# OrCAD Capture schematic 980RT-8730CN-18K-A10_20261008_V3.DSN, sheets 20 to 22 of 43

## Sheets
20 P0061_S6_DUT1: size Custom
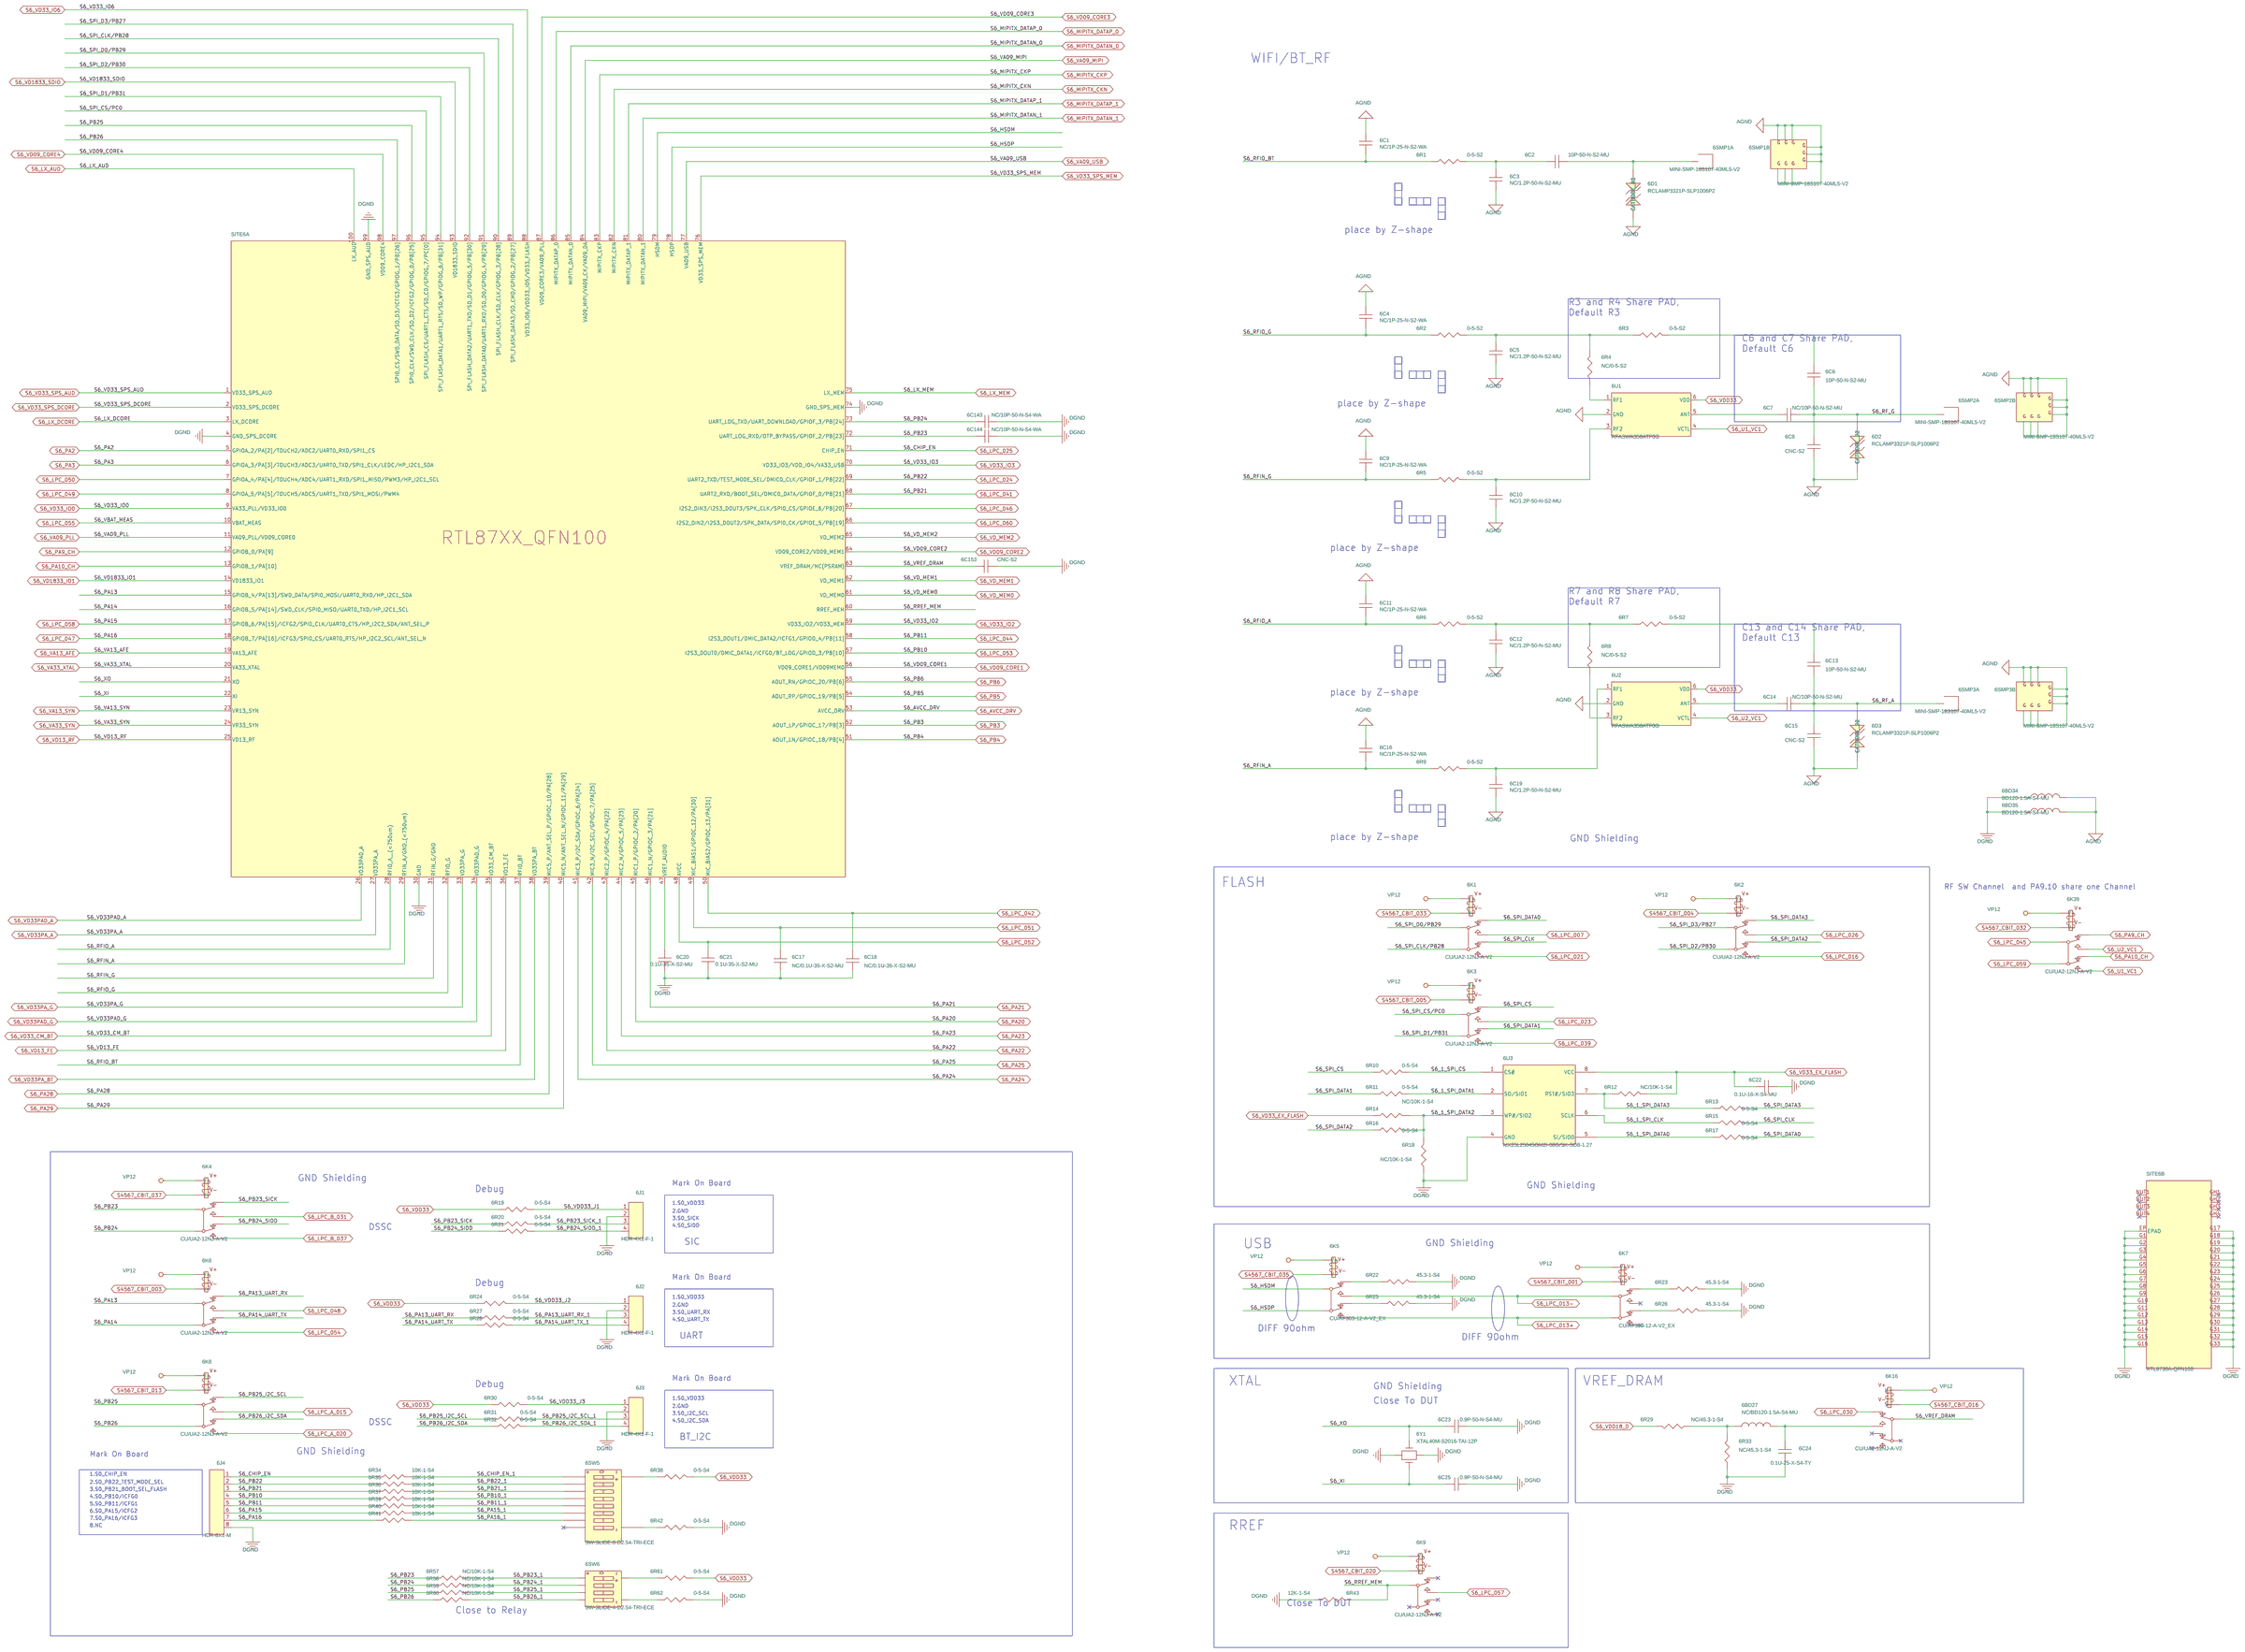
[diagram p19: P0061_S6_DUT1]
21 P0062_S6_Function-test: size A3
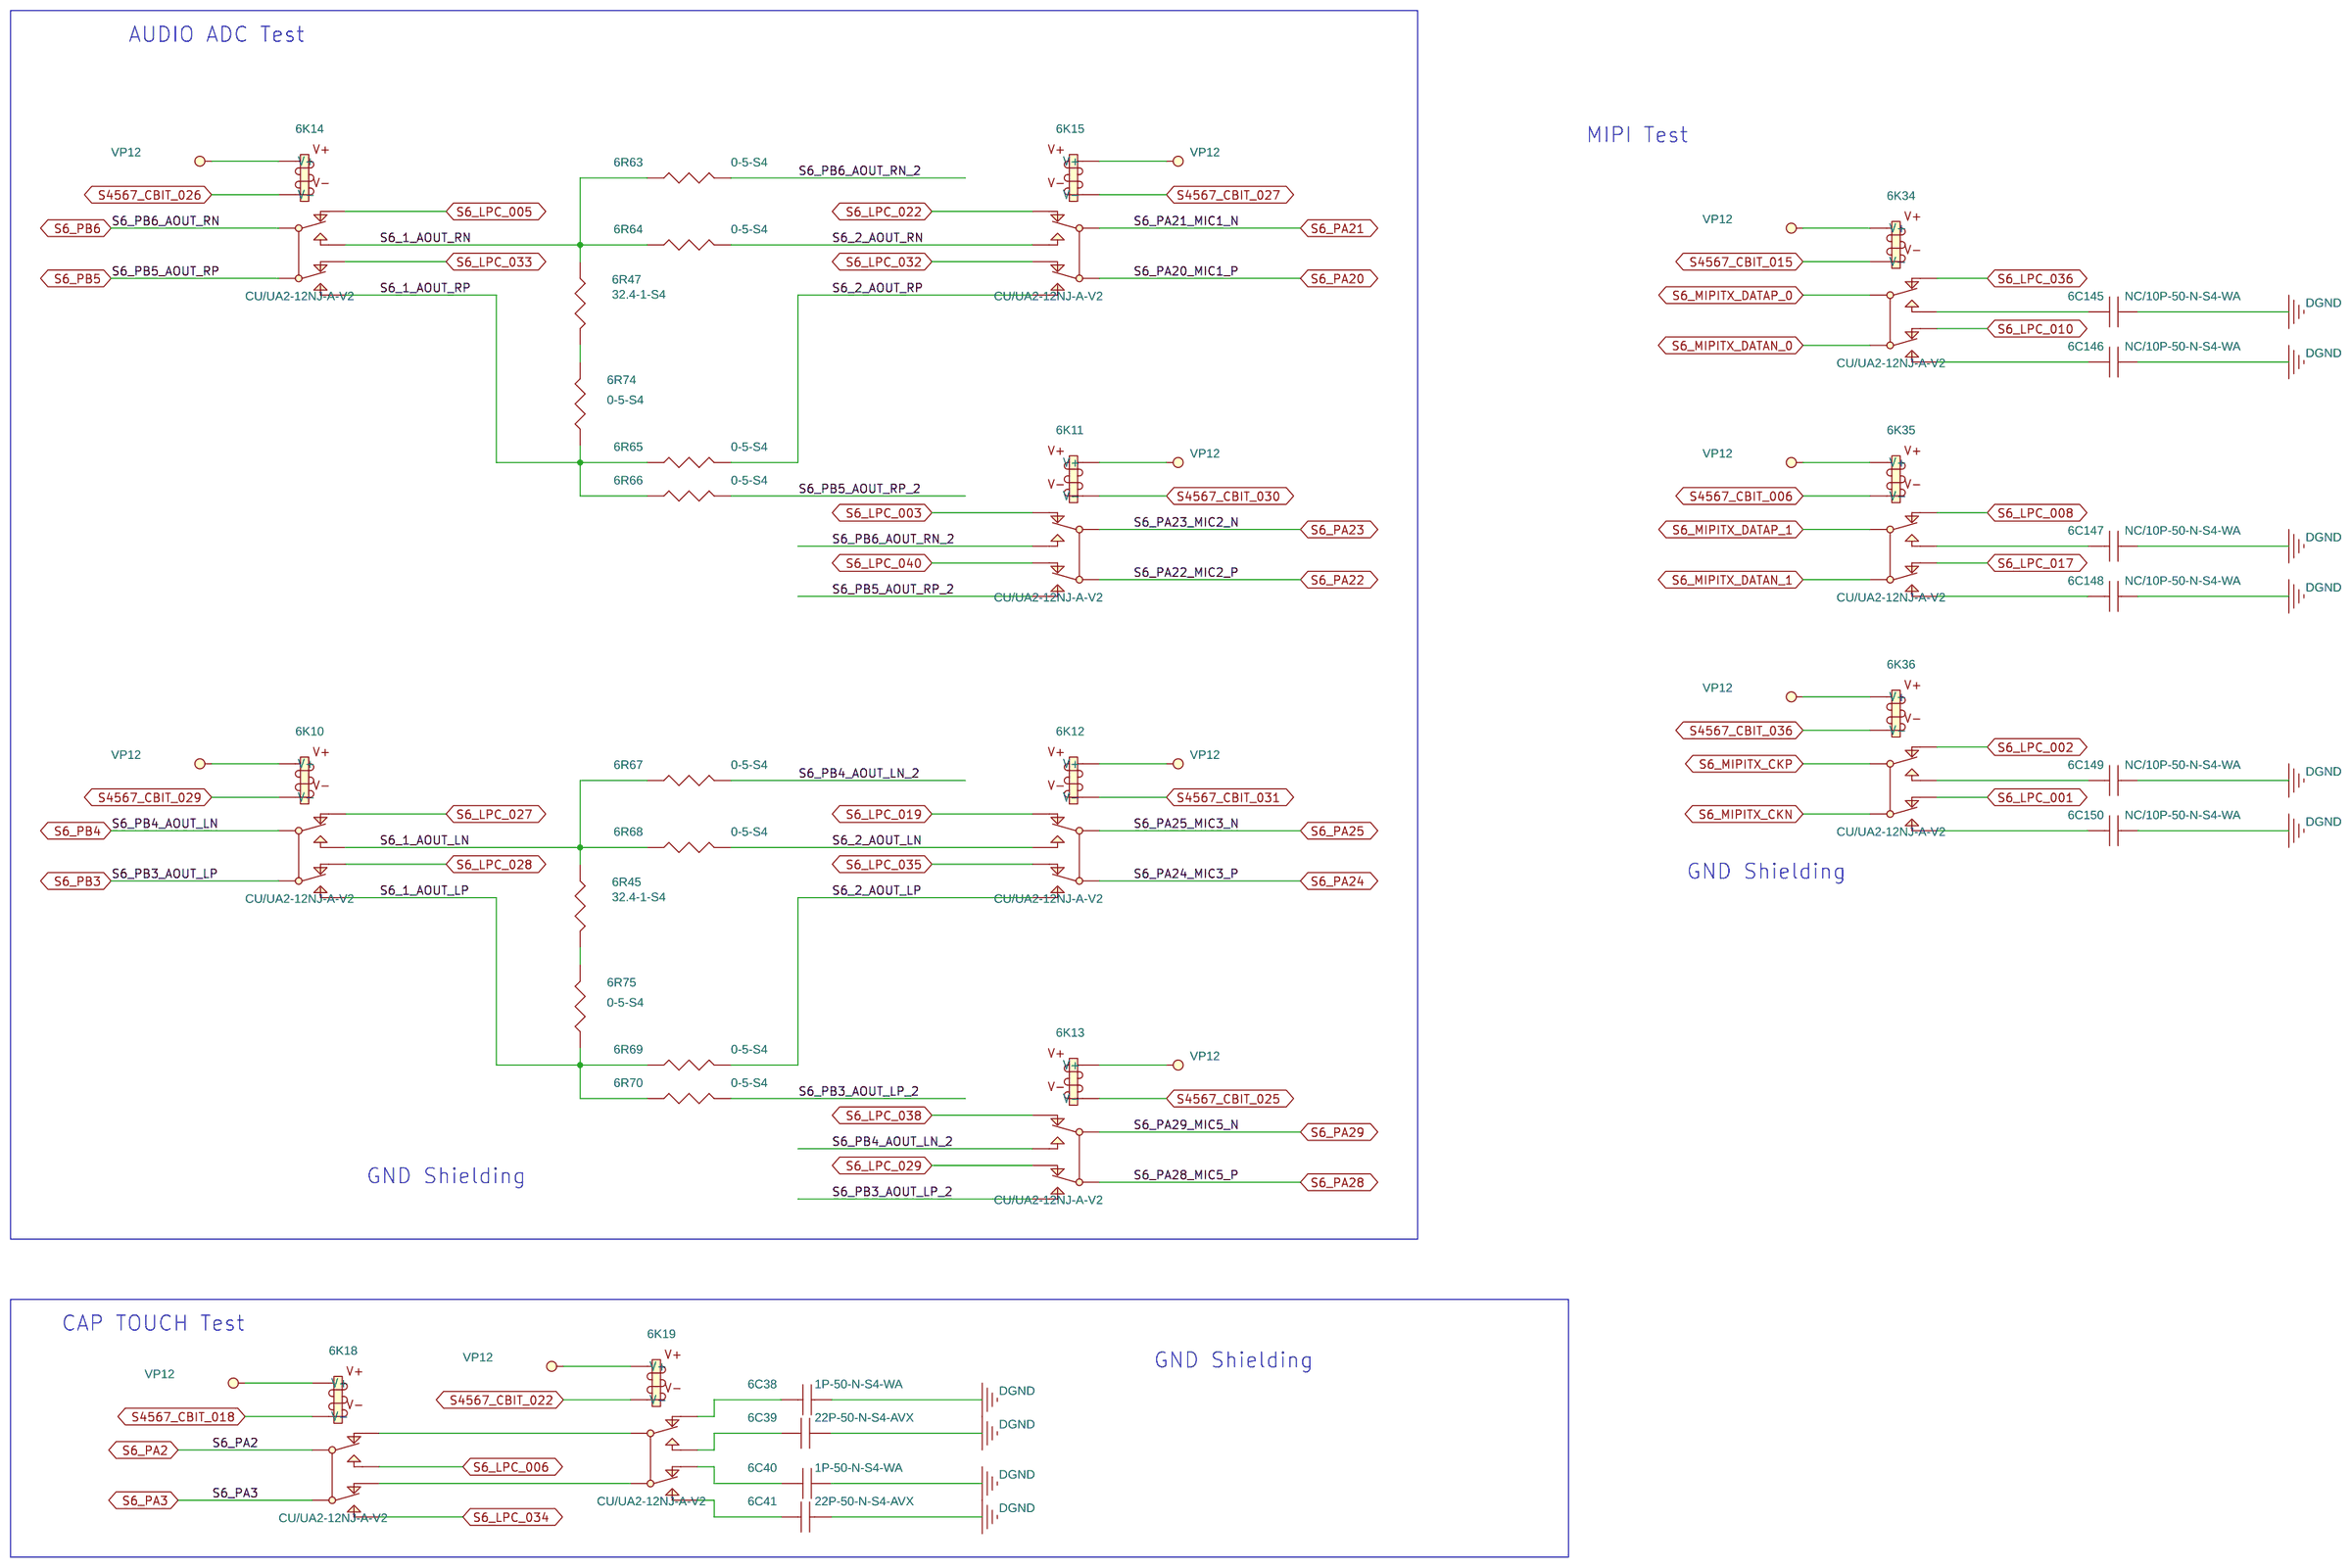
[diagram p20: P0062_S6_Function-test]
22 P0063_S6_Power: size A1
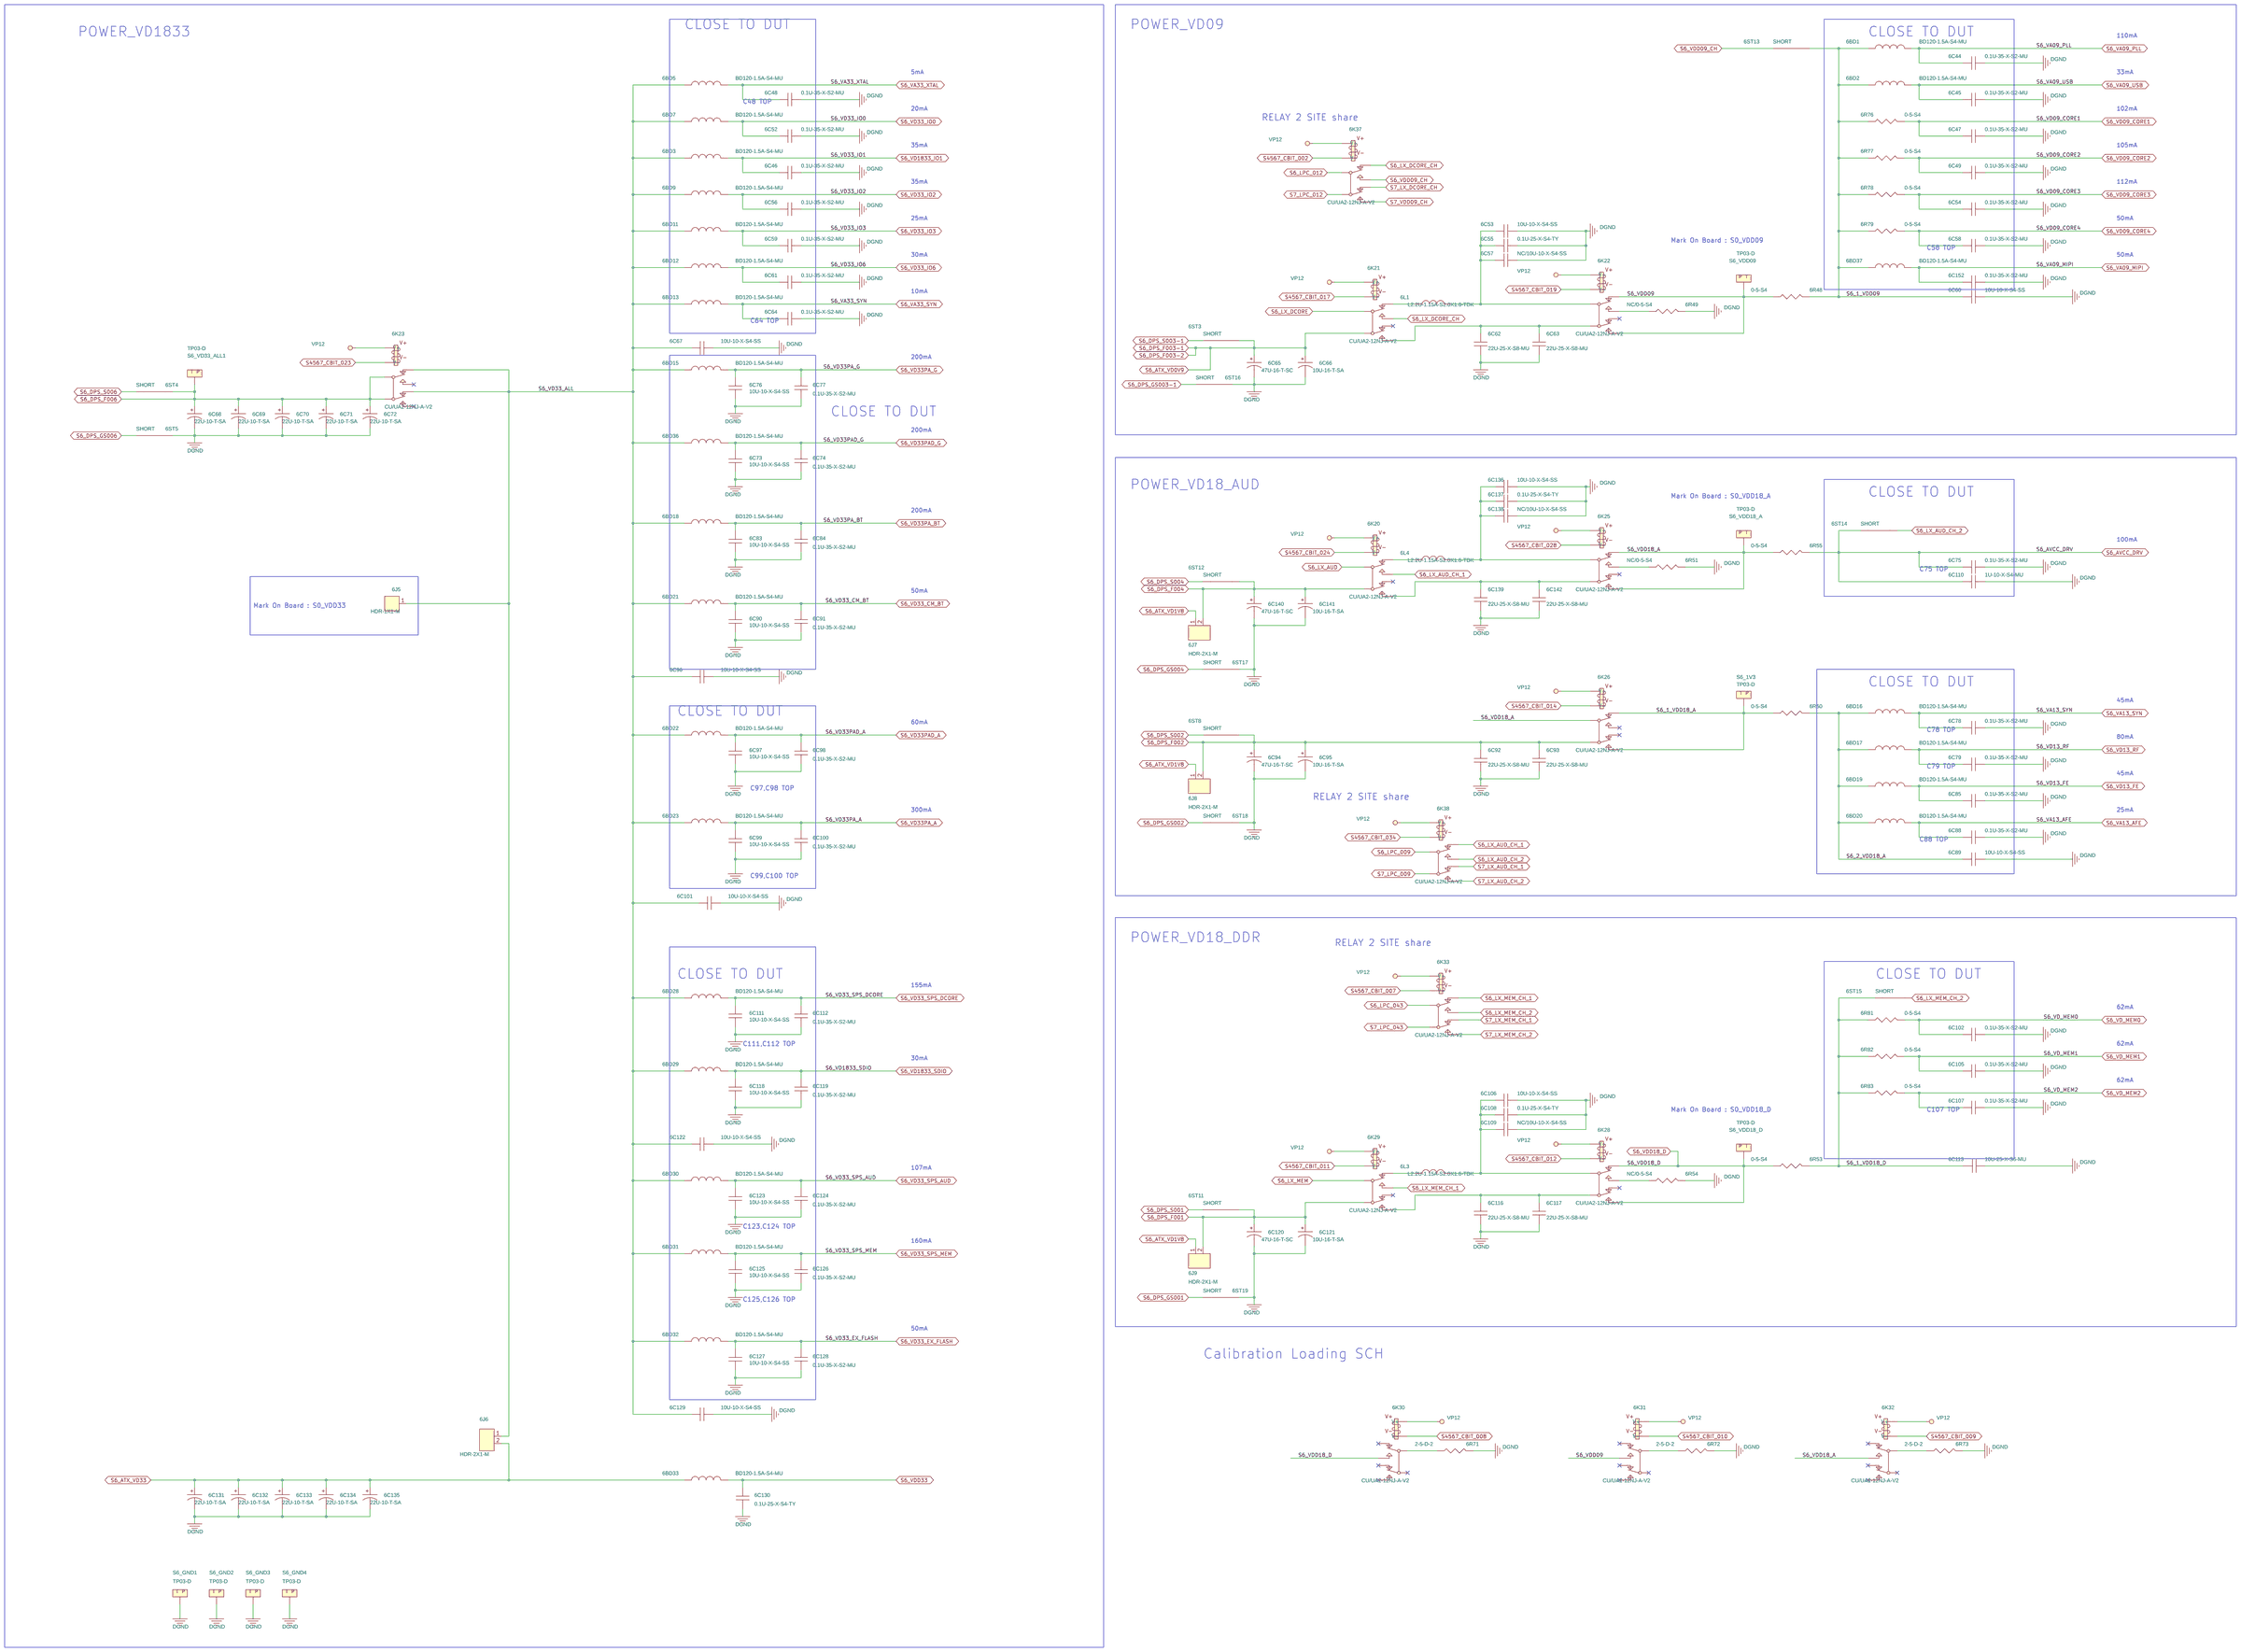
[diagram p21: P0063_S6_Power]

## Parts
sheet P0061_S6_DUT1
6BD27  NC/BD120-1.5A-S4-MU  [FB0402]
6BD34  BD120-1.5A-S4-MU  [FB0402]
6BD35  BD120-1.5A-S4-MU  [FB0402]
6C1  NC/1P-25-N-S2-WA  [C0201]
6C2  10P-50-N-S2-MU  [C0201]
6C3  NC/1.2P-50-N-S2-MU  [C0201]
6C4  NC/1P-25-N-S2-WA  [C0201]
6C5  NC/1.2P-50-N-S2-MU  [C0201]
6C6  10P-50-N-S2-MU  [C0201]
6C7  NC/10P-50-N-S2-MU  [C0201]
6C8  CNC-S2  [C0201]
6C9  NC/1P-25-N-S2-WA  [C0201]
6C10  NC/1.2P-50-N-S2-MU  [C0201]
6C11  NC/1P-25-N-S2-WA  [C0201]
6C12  NC/1.2P-50-N-S2-MU  [C0201]
6C13  10P-50-N-S2-MU  [C0201]
6C14  NC/10P-50-N-S2-MU  [C0201]
6C15  CNC-S2  [C0201]
6C16  NC/1P-25-N-S2-WA  [C0201]
6C17  NC/0.1U-35-X-S2-MU  [C0201]
6C18  NC/0.1U-35-X-S2-MU  [C0201]
6C19  NC/1.2P-50-N-S2-MU  [C0201]
6C20  0.1U-35-X-S2-MU  [C0201]
6C21  0.1U-35-X-S2-MU  [C0201]
6C22  0.1U-16-X-S4-MU  [C0402]
6C23  0.9P-50-N-S4-MU  [C0402]
6C24  0.1U-25-X-S4-TY  [C0402]
6C25  0.9P-50-N-S4-MU  [C0402]
6C143  NC/10P-50-N-S4-WA  [C0402]
6C144  NC/10P-50-N-S4-WA  [C0402]
6C153  CNC-S2  [C0201]
6D1  RCLAMP3321P-SLP1006P2  [DIODE_1X0P6MM]
6D2  RCLAMP3321P-SLP1006P2  [DIODE_1X0P6MM]
6D3  RCLAMP3321P-SLP1006P2  [DIODE_1X0P6MM]
6J1  HDR-4X1-F-1  [CONN_4X1_2P54MM_FL10P5MM]
6J2  HDR-4X1-F-1  [CONN_4X1_2P54MM_FL10P5MM]
6J3  HDR-4X1-F-1  [CONN_4X1_2P54MM_FL10P5MM]
6J4  HDR-8X1-M  [JP_8P_100]
6K1  CU/UA2-12NJ-A-V2  [RL_NECUA2_12V_V2]
6K2  CU/UA2-12NJ-A-V2  [RL_NECUA2_12V_V2]
6K3  CU/UA2-12NJ-A-V2  [RL_NECUA2_12V_V2]
6K4  CU/UA2-12NJ-A-V2  [RL_NECUA2_12V_V2]
6K5  CU/RF303-12-A-V2_EX  [RL_RF303_12V_V2]
6K6  CU/UA2-12NJ-A-V2  [RL_NECUA2_12V_V2]
6K7  CU/RF303-12-A-V2_EX  [RL_RF303_12V_V2]
6K8  CU/UA2-12NJ-A-V2  [RL_NECUA2_12V_V2]
6K9  CU/UA2-12NJ-A-V2  [RL_NECUA2_12V_V2]
6K16  CU/UA2-12NJ-A-V2  [RL_NECUA2_12V_V2]
6K39  CU/UA2-12NJ-A-V2  [RL_NECUA2_12V_V2]
6R1  0-5-S2  [R0201]
6R2  0-5-S2  [R0201]
6R3  0-5-S2  [R0201]
6R4  NC/0-5-S2  [R0201]
6R5  0-5-S2  [R0201]
6R6  0-5-S2  [R0201]
6R7  0-5-S2  [R0201]
6R8  NC/0-5-S2  [R0201]
6R9  0-5-S2  [R0201]
6R10  0-5-S4  [R0402]
6R11  0-5-S4  [R0402]
6R12  NC/10K-1-S4  [R0402]
6R13  0-5-S4  [R0402]
6R14  NC/10K-1-S4  [R0402]
6R15  0-5-S4  [R0402]
6R16  0-5-S4  [R0402]
6R17  0-5-S4  [R0402]
6R18  NC/10K-1-S4  [R0402]
6R19  0-5-S4  [R0402]
6R20  0-5-S4  [R0402]
6R21  0-5-S4  [R0402]
6R22  45.3-1-S4  [R0402]
6R23  45.3-1-S4  [R0402]
6R24  0-5-S4  [R0402]
6R25  45.3-1-S4  [R0402]
6R26  45.3-1-S4  [R0402]
6R27  0-5-S4  [R0402]
6R28  0-5-S4  [R0402]
6R29  NC/45.3-1-S4  [R0402]
6R30  0-5-S4  [R0402]
6R31  0-5-S4  [R0402]
6R32  0-5-S4  [R0402]
6R33  NC/45.3-1-S4  [R0402]
6R34  10K-1-S4  [R0402]
6R35  10K-1-S4  [R0402]
6R36  10K-1-S4  [R0402]
6R37  10K-1-S4  [R0402]
6R38  0-5-S4  [R0402]
6R39  10K-1-S4  [R0402]
6R40  10K-1-S4  [R0402]
6R41  10K-1-S4  [R0402]
6R42  0-5-S4  [R0402]
6R43  12K-1-S4  [R0402]
6R57  NC/10K-1-S4  [R0402]
6R58  NC/10K-1-S4  [R0402]
6R59  NC/10K-1-S4  [R0402]
6R60  NC/10K-1-S4  [R0402]
6R61  0-5-S4  [R0402]
6R62  0-5-S4  [R0402]
6SMP1  MINI-SMP-18S107-40ML5-V2  [CONN_SMP_18S107]  (sections A,B)
6SMP2  MINI-SMP-18S107-40ML5-V2  [CONN_SMP_18S107]  (sections A,B)
6SMP3  MINI-SMP-18S107-40ML5-V2  [CONN_SMP_18S107]  (sections A,B)
6SW5  SW-SLIDE-8-D2.54-TRI-ECE  [SW_DIPX8P_2P54_MM_V2]
6SW6  SW-SLIDE-4-D2.54-TRI-ECE  [SW_DIPX4P_2P54MM_ETD]
6U1  RFASWA358ATF0G  [RF_SW_GW2159_6P]
6U2  RFASWA358ATF0G  [RF_SW_GW2159_6P]
6U3  MX25L25645GM2I-08G/SK-SO8-1.27  [SK_SO8_1P27MM_LOTES]
6Y1  XTAL40M-S2016-TAI-12P  [XTAL_2X1P6MM_4P_0P8MM]
SITE6  RTL8730A-QFN100  [SK_QFN100P_0P35MM_MJC_L8730A]  (sections A,B)
sheet P0062_S6_Function-test
6C38  1P-50-N-S4-WA  [C0402]
6C39  22P-50-N-S4-AVX  [C0402]
6C40  1P-50-N-S4-WA  [C0402]
6C41  22P-50-N-S4-AVX  [C0402]
6C145  NC/10P-50-N-S4-WA  [C0402]
6C146  NC/10P-50-N-S4-WA  [C0402]
6C147  NC/10P-50-N-S4-WA  [C0402]
6C148  NC/10P-50-N-S4-WA  [C0402]
6C149  NC/10P-50-N-S4-WA  [C0402]
6C150  NC/10P-50-N-S4-WA  [C0402]
6K10  CU/UA2-12NJ-A-V2  [RL_NECUA2_12V_V2]
6K11  CU/UA2-12NJ-A-V2  [RL_NECUA2_12V_V2]
6K12  CU/UA2-12NJ-A-V2  [RL_NECUA2_12V_V2]
6K13  CU/UA2-12NJ-A-V2  [RL_NECUA2_12V_V2]
6K14  CU/UA2-12NJ-A-V2  [RL_NECUA2_12V_V2]
6K15  CU/UA2-12NJ-A-V2  [RL_NECUA2_12V_V2]
6K18  CU/UA2-12NJ-A-V2  [RL_NECUA2_12V_V2]
6K19  CU/UA2-12NJ-A-V2  [RL_NECUA2_12V_V2]
6K34  CU/UA2-12NJ-A-V2  [RL_NECUA2_12V_V2]
6K35  CU/UA2-12NJ-A-V2  [RL_NECUA2_12V_V2]
6K36  CU/UA2-12NJ-A-V2  [RL_NECUA2_12V_V2]
6R45  32.4-1-S4  [R0402]
6R47  32.4-1-S4  [R0402]
6R63  0-5-S4  [R0402]
6R64  0-5-S4  [R0402]
6R65  0-5-S4  [R0402]
6R66  0-5-S4  [R0402]
6R67  0-5-S4  [R0402]
6R68  0-5-S4  [R0402]
6R69  0-5-S4  [R0402]
6R70  0-5-S4  [R0402]
6R74  0-5-S4  [R0402]
6R75  0-5-S4  [R0402]
sheet P0063_S6_Power
6BD1  BD120-1.5A-S4-MU  [FB0402]
6BD2  BD120-1.5A-S4-MU  [FB0402]
6BD3  BD120-1.5A-S4-MU  [FB0402]
6BD5  BD120-1.5A-S4-MU  [FB0402]
6BD7  BD120-1.5A-S4-MU  [FB0402]
6BD9  BD120-1.5A-S4-MU  [FB0402]
6BD11  BD120-1.5A-S4-MU  [FB0402]
6BD12  BD120-1.5A-S4-MU  [FB0402]
6BD13  BD120-1.5A-S4-MU  [FB0402]
6BD15  BD120-1.5A-S4-MU  [FB0402]
6BD16  BD120-1.5A-S4-MU  [FB0402]
6BD17  BD120-1.5A-S4-MU  [FB0402]
6BD18  BD120-1.5A-S4-MU  [FB0402]
6BD19  BD120-1.5A-S4-MU  [FB0402]
6BD20  BD120-1.5A-S4-MU  [FB0402]
6BD21  BD120-1.5A-S4-MU  [FB0402]
6BD22  BD120-1.5A-S4-MU  [FB0402]
6BD23  BD120-1.5A-S4-MU  [FB0402]
6BD28  BD120-1.5A-S4-MU  [FB0402]
6BD29  BD120-1.5A-S4-MU  [FB0402]
6BD30  BD120-1.5A-S4-MU  [FB0402]
6BD31  BD120-1.5A-S4-MU  [FB0402]
6BD32  BD120-1.5A-S4-MU  [FB0402]
6BD33  BD120-1.5A-S4-MU  [FB0402]
6BD36  BD120-1.5A-S4-MU  [FB0402]
6BD37  BD120-1.5A-S4-MU  [FB0402]
6C44  0.1U-35-X-S2-MU  [C0201]
6C45  0.1U-35-X-S2-MU  [C0201]
6C46  0.1U-35-X-S2-MU  [C0201]
6C47  0.1U-35-X-S2-MU  [C0201]
6C48  0.1U-35-X-S2-MU  [C0201]
6C49  0.1U-35-X-S2-MU  [C0201]
6C52  0.1U-35-X-S2-MU  [C0201]
6C53  10U-10-X-S4-SS  [C0402]
6C54  0.1U-35-X-S2-MU  [C0201]
6C55  0.1U-25-X-S4-TY  [C0402]
6C56  0.1U-35-X-S2-MU  [C0201]
6C57  NC/10U-10-X-S4-SS  [C0402]
6C58  0.1U-35-X-S2-MU  [C0201]
6C59  0.1U-35-X-S2-MU  [C0201]
6C60  10U-10-X-S4-SS  [C0402]
6C61  0.1U-35-X-S2-MU  [C0201]
6C62  22U-25-X-S8-MU  [C0805]
6C63  22U-25-X-S8-MU  [C0805]
6C64  0.1U-35-X-S2-MU  [C0201]
6C65  47U-16-T-SC  [CODE_C]
6C66  10U-16-T-SA  [CODE_A]
6C67  10U-10-X-S4-SS  [C0402]
6C68  22U-10-T-SA  [CODE_A]
6C69  22U-10-T-SA  [CODE_A]
6C70  22U-10-T-SA  [CODE_A]
6C71  22U-10-T-SA  [CODE_A]
6C72  22U-10-T-SA  [CODE_A]
6C73  10U-10-X-S4-SS  [C0402]
6C74  0.1U-35-X-S2-MU  [C0201]
6C75  0.1U-35-X-S2-MU  [C0201]
6C76  10U-10-X-S4-SS  [C0402]
6C77  0.1U-35-X-S2-MU  [C0201]
6C78  0.1U-35-X-S2-MU  [C0201]
6C79  0.1U-35-X-S2-MU  [C0201]
6C83  10U-10-X-S4-SS  [C0402]
6C84  0.1U-35-X-S2-MU  [C0201]
6C85  0.1U-35-X-S2-MU  [C0201]
6C88  0.1U-35-X-S2-MU  [C0201]
6C89  10U-10-X-S4-SS  [C0402]
6C90  10U-10-X-S4-SS  [C0402]
6C91  0.1U-35-X-S2-MU  [C0201]
6C92  22U-25-X-S8-MU  [C0805]
6C93  22U-25-X-S8-MU  [C0805]
6C94  47U-16-T-SC  [CODE_C]
6C95  10U-16-T-SA  [CODE_A]
6C96  10U-10-X-S4-SS  [C0402]
6C97  10U-10-X-S4-SS  [C0402]
6C98  0.1U-35-X-S2-MU  [C0201]
6C99  10U-10-X-S4-SS  [C0402]
6C100  0.1U-35-X-S2-MU  [C0201]
6C101  10U-10-X-S4-SS  [C0402]
6C102  0.1U-35-X-S2-MU  [C0201]
6C105  0.1U-35-X-S2-MU  [C0201]
6C106  10U-10-X-S4-SS  [C0402]
6C107  0.1U-35-X-S2-MU  [C0201]
6C108  0.1U-25-X-S4-TY  [C0402]
6C109  NC/10U-10-X-S4-SS  [C0402]
6C110  1U-10-X-S4-MU  [C0402]
6C111  10U-10-X-S4-SS  [C0402]
6C112  0.1U-35-X-S2-MU  [C0201]
6C113  10U-25-X-S6-MU  [C0603]
6C116  22U-25-X-S8-MU  [C0805]
6C117  22U-25-X-S8-MU  [C0805]
6C118  10U-10-X-S4-SS  [C0402]
6C119  0.1U-35-X-S2-MU  [C0201]
6C120  47U-16-T-SC  [CODE_C]
6C121  10U-16-T-SA  [CODE_A]
6C122  10U-10-X-S4-SS  [C0402]
6C123  10U-10-X-S4-SS  [C0402]
6C124  0.1U-35-X-S2-MU  [C0201]
6C125  10U-10-X-S4-SS  [C0402]
6C126  0.1U-35-X-S2-MU  [C0201]
6C127  10U-10-X-S4-SS  [C0402]
6C128  0.1U-35-X-S2-MU  [C0201]
6C129  10U-10-X-S4-SS  [C0402]
6C130  0.1U-25-X-S4-TY  [C0402]
6C131  22U-10-T-SA  [CODE_A]
6C132  22U-10-T-SA  [CODE_A]
6C133  22U-10-T-SA  [CODE_A]
6C134  22U-10-T-SA  [CODE_A]
6C135  22U-10-T-SA  [CODE_A]
6C136  10U-10-X-S4-SS  [C0402]
6C137  0.1U-25-X-S4-TY  [C0402]
6C138  NC/10U-10-X-S4-SS  [C0402]
6C139  22U-25-X-S8-MU  [C0805]
6C140  47U-16-T-SC  [CODE_C]
6C141  10U-16-T-SA  [CODE_A]
6C142  22U-25-X-S8-MU  [C0805]
6C152  0.1U-35-X-S2-MU  [C0201]
6J5  HDR-1X1-M  [JP_1P_RD070_040]
6J6  HDR-2X1-M  [JP_2P_100]
6J7  HDR-2X1-M  [JP_2P_100]
6J8  HDR-2X1-M  [JP_2P_100]
6J9  HDR-2X1-M  [JP_2P_100]
6K20  CU/UA2-12NJ-A-V2  [RL_NECUA2_12V_V2]
6K21  CU/UA2-12NJ-A-V2  [RL_NECUA2_12V_V2]
6K22  CU/UA2-12NJ-A-V2  [RL_NECUA2_12V_V2]
6K23  CU/UA2-12NJ-A-V2  [RL_NECUA2_12V_V2]
6K25  CU/UA2-12NJ-A-V2  [RL_NECUA2_12V_V2]
6K26  CU/UA2-12NJ-A-V2  [RL_NECUA2_12V_V2]
6K28  CU/UA2-12NJ-A-V2  [RL_NECUA2_12V_V2]
6K29  CU/UA2-12NJ-A-V2  [RL_NECUA2_12V_V2]
6K30  CU/UA2-12NJ-A-V2  [RL_NECUA2_12V_V2]
6K31  CU/UA2-12NJ-A-V2  [RL_NECUA2_12V_V2]
6K32  CU/UA2-12NJ-A-V2  [RL_NECUA2_12V_V2]
6K33  CU/UA2-12NJ-A-V2  [RL_NECUA2_12V_V2]
6K37  CU/UA2-12NJ-A-V2  [RL_NECUA2_12V_V2]
6K38  CU/UA2-12NJ-A-V2  [RL_NECUA2_12V_V2]
6L1  L2.2U-1.15A-S2.0X1.6-TDK  [IND_VL252012E]
6L3  L2.2U-1.15A-S2.0X1.6-TDK  [IND_VL252012E]
6L4  L2.2U-1.15A-S2.0X1.6-TDK  [IND_VL252012E]
6R48  0-5-S4  [R0402]
6R49  NC/0-5-S4  [R0402]
6R50  0-5-S4  [R0402]
6R51  NC/0-5-S4  [R0402]
6R53  0-5-S4  [R0402]
6R54  NC/0-5-S4  [R0402]
6R55  0-5-S4  [R0402]
6R71  2-5-D-2  [RC02W_27MM]
6R72  2-5-D-2  [RC02W_27MM]
6R73  2-5-D-2  [RC02W_27MM]
6R76  0-5-S4  [R0402]
6R77  0-5-S4  [R0402]
6R78  0-5-S4  [R0402]
6R79  0-5-S4  [R0402]
6R81  0-5-S4  [R0402]
6R82  0-5-S4  [R0402]
6R83  0-5-S4  [R0402]
6ST3  SHORT  [DEFAULT_SHORT_SMALL]
6ST4  SHORT  [DEFAULT_SHORT_SMALL]
6ST5  SHORT  [DEFAULT_SHORT_SMALL]
6ST8  SHORT  [DEFAULT_SHORT_SMALL]
6ST11  SHORT  [DEFAULT_SHORT_SMALL]
6ST12  SHORT  [DEFAULT_SHORT_SMALL]
6ST13  SHORT  [DEFAULT_SHORT_SMALL]
6ST14  SHORT  [DEFAULT_SHORT_SMALL]
6ST15  SHORT  [DEFAULT_SHORT_SMALL]
6ST16  SHORT  [DEFAULT_SHORT_SMALL]
6ST17  SHORT  [DEFAULT_SHORT_SMALL]
6ST18  SHORT  [DEFAULT_SHORT_SMALL]
6ST19  SHORT  [DEFAULT_SHORT_SMALL]
S6_1V3  TP03-D  [TP_060_040]
S6_GND1  TP03-D  [TP_060_040]
S6_GND2  TP03-D  [TP_060_040]
S6_GND3  TP03-D  [TP_060_040]
S6_GND4  TP03-D  [TP_060_040]
S6_VD33_ALL1  TP03-D  [TP_060_040]
S6_VDD09  TP03-D  [TP_060_040]
S6_VDD18_A  TP03-D  [TP_060_040]
S6_VDD18_D  TP03-D  [TP_060_040]

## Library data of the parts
6BD27 = BD120-1.5A-S4-MU: KAIROSNAME: BD27
6BD34 = BD120-1.5A-S4-MU: KAIROSNAME: BD34
6BD35 = BD120-1.5A-S4-MU: KAIROSNAME: BD35
6C1 6C4 6C9 6C11 6C16 = 1P-25-N-S2-WA
6C2 6C6 6C7 6C13 6C14 = 10P-50-N-S2-MU
6C3 6C5 6C10 6C12 6C19 = 1.2P-50-N-S2-MU
6C8 6C15 = CNC-S4
6C17 6C18 6C46 = 0.1U-35-X-S2-MU: KAIROSNAME: C46
6C20 6C21 6C98 = 0.1U-35-X-S2-MU: KAIROSNAME: C98
6C22 = 0.1U-16-X-S4: KAIROSNAME: C22
6C23 = 10P-50-N-S4-MU-1: KAIROSNAME: C23
6C24 = 0.1U-25-X-S4-TY: KAIROSNAME: C24
6C25 = 10P-50-N-S4-MU-1: KAIROSNAME: C25
6C143-6C150 = 10P-50-N-S4-WA
6C48 6C153 = 0.1U-35-X-S2-MU: KAIROSNAME: C48
6D1 = RCLAMP3321P-SLP1006P2: KAIROSNAME: D1
6D2 = RCLAMP3321P-SLP1006P2: KAIROSNAME: D2
6D3 = RCLAMP3321P-SLP1006P2: KAIROSNAME: D3
6J1-6J3 = HDR-4X1-F-1
6J4 = HDR-8X1-M: KAIROSNAME: J4
6K1 6K39 = CU_UA2-12NJ-A-V2: KAIROSNAME: K1
6K2 6K16 = CU_UA2-12NJ-A-V2: KAIROSNAME: K2
6K3 = CU_UA2-12NJ-A-V2: KAIROSNAME: K3
6K4 = CU_UA2-12NJ-A-V2: KAIROSNAME: K4
6K5 = CU_RF303-12-A-V2_EX: KAIROSNAME: K5
6K6 = CU_UA2-12NJ-A-V2: KAIROSNAME: K6
6K7 = CU_RF303-12-A-V2_EX: KAIROSNAME: K7
6K8 = CU_UA2-12NJ-A-V2: KAIROSNAME: K8
6K9 = CU_UA2-12NJ-A-V2: KAIROSNAME: K9
6R1-6R9 = 0-5-S2
6R10 = 0-5-S4: KAIROSNAME: R10
6R11 = 0-5-S4: KAIROSNAME: R11
6R12 = 10K-1-S4: KAIROSNAME: R12
6R13 = 0-5-S4: KAIROSNAME: R13
6R14 = 10K-1-S4: KAIROSNAME: R14
6R15 = 0-5-S4: KAIROSNAME: R15
6R16 = 0-5-S4: KAIROSNAME: R16
6R17 = 0-5-S4: KAIROSNAME: R17
6R18 = 10K-1-S4: KAIROSNAME: R18
6R19 = 0-5-S4: KAIROSNAME: R19
6R20 = 0-5-S4: KAIROSNAME: R20
6R21 = 0-5-S4: KAIROSNAME: R21
6R22 = 45.3-1-S4: KAIROSNAME: R22
6R23 = 45.3-1-S4: KAIROSNAME: R23
6R24 = 0-5-S4: KAIROSNAME: R24
6R25 = 45.3-1-S4: KAIROSNAME: R25
6R26 = 45.3-1-S4: KAIROSNAME: R26
6R27 = 0-5-S4: KAIROSNAME: R27
6R28 = 0-5-S4: KAIROSNAME: R28
6R29 = 45.3-1-S4: KAIROSNAME: R29
6R30 = 0-5-S4: KAIROSNAME: R30
6R31 = 0-5-S4: KAIROSNAME: R31
6R32 = 0-5-S4: KAIROSNAME: R32
6R33 = 45.3-1-S4: KAIROSNAME: R33
6R34 = 10K-1-S4: KAIROSNAME: R34
6R35 = 10K-1-S4: KAIROSNAME: R35
6R36 = 10K-1-S4: KAIROSNAME: R36
6R37 = 10K-1-S4: KAIROSNAME: R37
6R38 = 0-5-S4: KAIROSNAME: R38
6R39 = 10K-1-S4: KAIROSNAME: R39
6R40 = 10K-1-S4: KAIROSNAME: R40
6R41 = 10K-1-S4: KAIROSNAME: R41
6R42 = 0-5-S4: KAIROSNAME: R42
6R43 = 12K-1-S4: KAIROSNAME: R43
6R57 = 10K-1-S4: KAIROSNAME: R57
6R58 = 10K-1-S4: KAIROSNAME: R58
6R59 = 10K-1-S4: KAIROSNAME: R59
6R60 = 10K-1-S4: KAIROSNAME: R60
6R61 = 0-5-S4: KAIROSNAME: R61
6R62 = 0-5-S4: KAIROSNAME: R62
6SMP1 = MINI-SMP-18S107-40ML5-V2: KAIROSNAME: SMP1A
6SMP2 = MINI-SMP-18S107-40ML5-V2: KAIROSNAME: SMP2A
6SMP3 = MINI-SMP-18S107-40ML5-V2: KAIROSNAME: SMP3B
6SW5 = SW-SLIDE-8-D2.54-TRI-ECE
6SW6 = SW-SLIDE-4-D2.54-TRI-ECE
6U1 6U2 = RFASWA358ATF0G
6U3 = MX25R6435FM2IL0-SOP8: KAIROSNAME: U3
6Y1 = XTAL40M-S2016-TAI-12P: KAIROSNAME: Y1
SITE6 = RTL8730A-QFN100
6C38 = 10P-50-N-S4-MU-1: KAIROSNAME: C38
6C39 = 33P-50-N-S4-WA: KAIROSNAME: C39
6C40 = 10P-50-N-S4-MU-1: KAIROSNAME: C40
6C41 = 33P-50-N-S4-WA: KAIROSNAME: C41
6K10 = CU_UA2-12NJ-A-V2: KAIROSNAME: K10
6K11 = CU_UA2-12NJ-A-V2: KAIROSNAME: K11
6K12 = CU_UA2-12NJ-A-V2: KAIROSNAME: K12
6K13 = CU_UA2-12NJ-A-V2: KAIROSNAME: K13
6K14 = CU_UA2-12NJ-A-V2: KAIROSNAME: K14
6K15 6K34-6K36 = CU_UA2-12NJ-A-V2: KAIROSNAME: K15
6K18 = CU_UA2-12NJ-A-V2: KAIROSNAME: K18
6K19 = CU_UA2-12NJ-A-V2: KAIROSNAME: K19
6R45 = 32.4-1-S4: KAIROSNAME: R45
6R47 = 32.4-1-S4: KAIROSNAME: R47
6R63 = 0-5-S4: KAIROSNAME: R63
6R64 = 0-5-S4: KAIROSNAME: R64
6R65 6R74 6R75 = 0-5-S4: KAIROSNAME: R65
6R66 = 0-5-S4: KAIROSNAME: R66
6R67 = 0-5-S4: KAIROSNAME: R67
6R68 = 0-5-S4: KAIROSNAME: R68
6R69 = 0-5-S4: KAIROSNAME: R69
6R70 = 0-5-S4: KAIROSNAME: R70
6BD1 = BD120-1.5A-S4-MU: KAIROSNAME: BD1
6BD2 = BD120-1.5A-S4-MU: KAIROSNAME: BD2
6BD3 = BD120-1.5A-S4-MU: KAIROSNAME: BD3
6BD5 = BD120-1.5A-S4-MU: KAIROSNAME: BD5
6BD7 = BD120-1.5A-S4-MU: KAIROSNAME: BD7
6BD9 = BD120-1.5A-S4-MU: KAIROSNAME: BD9
6BD11 = BD120-1.5A-S4-MU: KAIROSNAME: BD11
6BD12 = BD120-1.5A-S4-MU: KAIROSNAME: BD12
6BD13 = BD120-1.5A-S4-MU: KAIROSNAME: BD13
6BD15 6BD36 = BD120-1.5A-S4-MU: KAIROSNAME: BD15
6BD16 = BD120-1.5A-S4-MU: KAIROSNAME: BD16
6BD17 = BD120-1.5A-S4-MU: KAIROSNAME: BD17
6BD18 = BD120-1.5A-S4-MU: KAIROSNAME: BD18
6BD19 = BD120-1.5A-S4-MU: KAIROSNAME: BD19
6BD20 = BD120-1.5A-S4-MU: KAIROSNAME: BD20
6BD21 = BD120-1.5A-S4-MU: KAIROSNAME: BD21
6BD22 = BD120-1.5A-S4-MU: KAIROSNAME: BD22
6BD23 = BD120-1.5A-S4-MU: KAIROSNAME: BD23
6BD28 = BD120-1.5A-S4-MU: KAIROSNAME: BD28
6BD29 = BD120-1.5A-S4-MU: KAIROSNAME: BD29
6BD30 = BD120-1.5A-S4-MU: KAIROSNAME: BD30
6BD31 = BD120-1.5A-S4-MU: KAIROSNAME: BD31
6BD32 = BD120-1.5A-S4-MU: KAIROSNAME: BD32
6BD33 = BD120-1.5A-S4-MU: KAIROSNAME: BD33
6BD37 = BD120-1.5A-S4-MU: KAIROSNAME: BD10
6C44 = 0.1U-35-X-S2-MU: KAIROSNAME: C44
6C45 = 0.1U-35-X-S2-MU: KAIROSNAME: C45
6C47 = 0.1U-35-X-S2-MU: KAIROSNAME: C47
6C49 = 0.1U-35-X-S2-MU: KAIROSNAME: C49
6C52 = 0.1U-35-X-S2-MU: KAIROSNAME: C52
6C53 = 10U-10-X-S4-SS: KAIROSNAME: C53
6C54 = 0.1U-35-X-S2-MU: KAIROSNAME: C54
6C55 = 0.1U-25-X-S4-TY: KAIROSNAME: C55
6C56 = 0.1U-35-X-S2-MU: KAIROSNAME: C56
6C57 = 10U-10-X-S4-SS: KAIROSNAME: C57
6C58 6C152 = 0.1U-35-X-S2-MU: KAIROSNAME: C58
6C59 = 0.1U-35-X-S2-MU: KAIROSNAME: C59
6C60 = 10U-10-X-S4-SS: KAIROSNAME: C60
6C61 = 0.1U-35-X-S2-MU: KAIROSNAME: C61
6C62 = 22U-25-X-S8-MU: KAIROSNAME: C62
6C63 = 22U-25-X-S8-MU: KAIROSNAME: C63
6C64 = 0.1U-35-X-S2-MU: KAIROSNAME: C64
6C65 = 47U-16-T-SC: KAIROSNAME: C65
6C66 = 10U-16-T-SA: KAIROSNAME: C66
6C67 = 10U-10-X-S4-SS: KAIROSNAME: C67
6C68 = 22U-10-T-SA: KAIROSNAME: C68
6C69 = 22U-10-T-SA: KAIROSNAME: C69
6C70 = 22U-10-T-SA: KAIROSNAME: C70
6C71 = 22U-10-T-SA: KAIROSNAME: C71
6C72 = 22U-10-T-SA: KAIROSNAME: C72
6C73 6C76 = 10U-10-X-S4-SS: KAIROSNAME: C76
6C74 6C77 = 0.1U-35-X-S2-MU: KAIROSNAME: C77
6C75 = 0.1U-35-X-S2-MU: KAIROSNAME: C75
6C78 = 0.1U-35-X-S2-MU: KAIROSNAME: C78
6C79 = 0.1U-35-X-S2-MU: KAIROSNAME: C79
6C83 = 10U-10-X-S4-SS: KAIROSNAME: C83
6C84 = 0.1U-35-X-S2-MU: KAIROSNAME: C84
6C85 = 0.1U-35-X-S2-MU: KAIROSNAME: C85
6C88 = 0.1U-35-X-S2-MU: KAIROSNAME: C88
6C89 = 10U-10-X-S4-SS: KAIROSNAME: C89
6C90 = 10U-10-X-S4-SS: KAIROSNAME: C90
6C91 = 0.1U-35-X-S2-MU: KAIROSNAME: C91
6C92 = 22U-25-X-S8-MU: KAIROSNAME: C92
6C93 = 22U-25-X-S8-MU: KAIROSNAME: C93
6C94 = 47U-16-T-SC: KAIROSNAME: C94
6C95 = 10U-16-T-SA: KAIROSNAME: C95
6C96 = 10U-10-X-S4-SS: KAIROSNAME: C96
6C97 = 10U-10-X-S4-SS: KAIROSNAME: C97
6C99 = 10U-10-X-S4-SS: KAIROSNAME: C99
6C100 = 0.1U-35-X-S2-MU: KAIROSNAME: C100
6C101 = 10U-10-X-S4-SS: KAIROSNAME: C101
6C102 = 0.1U-35-X-S2-MU: KAIROSNAME: C102
6C105 = 0.1U-35-X-S2-MU: KAIROSNAME: C105
6C106 = 10U-10-X-S4-SS: KAIROSNAME: C106
6C107 = 0.1U-35-X-S2-MU: KAIROSNAME: C107
6C108 = 0.1U-25-X-S4-TY: KAIROSNAME: C108
6C109 = 10U-10-X-S4-SS: KAIROSNAME: C109
6C110 = 10U-10-X-S4-SS: KAIROSNAME: C110
6C111 = 10U-10-X-S4-SS: KAIROSNAME: C111
6C112 = 0.1U-35-X-S2-MU: KAIROSNAME: C112
6C113 = 10U-25-X-S6-MU: KAIROSNAME: C113
6C116 = 22U-25-X-S8-MU: KAIROSNAME: C116
6C117 = 22U-25-X-S8-MU: KAIROSNAME: C117
6C118 = 10U-10-X-S4-SS: KAIROSNAME: C118
6C119 = 0.1U-35-X-S2-MU: KAIROSNAME: C119
6C120 = 47U-16-T-SC: KAIROSNAME: C120
6C121 = 10U-16-T-SA: KAIROSNAME: C121
6C122 = 10U-10-X-S4-SS: KAIROSNAME: C122
6C123 = 10U-10-X-S4-SS: KAIROSNAME: C123
6C124 = 0.1U-35-X-S2-MU: KAIROSNAME: C124
6C125 = 10U-10-X-S4-SS: KAIROSNAME: C125
6C126 = 0.1U-35-X-S2-MU: KAIROSNAME: C126
6C127 = 10U-10-X-S4-SS: KAIROSNAME: C127
6C128 = 0.1U-35-X-S2-MU: KAIROSNAME: C128
6C129 = 10U-10-X-S4-SS: KAIROSNAME: C129
6C130 = 0.1U-25-X-S4-TY: KAIROSNAME: C130
6C131 = 22U-10-T-SA: KAIROSNAME: C131
6C132 = 22U-10-T-SA: KAIROSNAME: C132
6C133 = 22U-10-T-SA: KAIROSNAME: C133
6C134 = 22U-10-T-SA: KAIROSNAME: C134
6C135 = 22U-10-T-SA: KAIROSNAME: C135
6C136 = 10U-10-X-S4-SS: KAIROSNAME: C136
6C137 = 0.1U-25-X-S4-TY: KAIROSNAME: C137
6C138 = 10U-10-X-S4-SS: KAIROSNAME: C138
6C139 = 22U-25-X-S8-MU: KAIROSNAME: C139
6C140 = 47U-16-T-SC: KAIROSNAME: C140
6C141 = 10U-16-T-SA: KAIROSNAME: C141
6C142 = 22U-25-X-S8-MU: KAIROSNAME: C142
6J5 = HDR-1X1-M: KAIROSNAME: J5
6J6 = HDR-2X1-M: KAIROSNAME: J6
6J7 = HDR-2X1-M: KAIROSNAME: J7
6J8 = HDR-2X1-M: KAIROSNAME: J8
6J9 = HDR-2X1-M: KAIROSNAME: J9
6K20 = CU_UA2-12NJ-A-V2: KAIROSNAME: K20
6K21 = CU_UA2-12NJ-A-V2: KAIROSNAME: K21
6K22 6K37 6K38 = CU_UA2-12NJ-A-V2: KAIROSNAME: K22
6K23 = CU_UA2-12NJ-A-V2: KAIROSNAME: K23
6K25 = CU_UA2-12NJ-A-V2: KAIROSNAME: K25
6K26 6K33 = CU_UA2-12NJ-A-V2: KAIROSNAME: K26
6K28 6K30-6K32 = CU_UA2-12NJ-A-V2: KAIROSNAME: K28
6K29 = CU_UA2-12NJ-A-V2: KAIROSNAME: K29
6L1 = L2.2U-1.15A-S2.0X1.6-TDK: KAIROSNAME: L1
6L3 = L2.2U-1.15A-S2.0X1.6-TDK: KAIROSNAME: L3
6L4 = L2.2U-1.15A-S2.0X1.6-TDK: KAIROSNAME: L4
6R48 = 0-5-S4: KAIROSNAME: R48
6R49 = 0-5-S4: KAIROSNAME: R49
6R50 = 0-5-S4: KAIROSNAME: R50
6R51 = 0-5-S4: KAIROSNAME: R51
6R53 = 0-5-S4: KAIROSNAME: R53
6R54 = 0-5-S4: KAIROSNAME: R54
6R55 = 0-5-S4: KAIROSNAME: R55
6R71-6R73 = 2-5-D-2
6R76-6R79 6R81-6R83 = 0-5-S4
6ST3 6ST13-6ST15 = SHORT: KAIROSNAME: ST3
6ST4 = SHORT: KAIROSNAME: ST4
6ST5 6ST16-6ST19 = SHORT: KAIROSNAME: ST5
6ST8 = SHORT: KAIROSNAME: ST8
6ST11 = SHORT: KAIROSNAME: ST11
6ST12 = SHORT: KAIROSNAME: ST12
S6_1V3 = TP03-D: KAIROSNAME: S0_TP_VD3
S6_GND1 = TP03-D: KAIROSNAME: S0_GND1
S6_GND2 = TP03-D: KAIROSNAME: S0_GND2
S6_GND3 = TP03-D: KAIROSNAME: S0_GND3
S6_GND4 = TP03-D: KAIROSNAME: S0_GND4
S6_VD33_ALL1 = TP03-D: KAIROSNAME: S0_VD33_ALL1
S6_VDD09 = TP03-D: KAIROSNAME: S0_VDD09
S6_VDD18_A = TP03-D: KAIROSNAME: S0_VDD18_A
S6_VDD18_D = TP03-D: KAIROSNAME: S0_VDD18_D

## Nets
AGND: 6BD34.2 6BD35.2 6C1.1 6C3.2 6C4.1 6C5.2 6C8.2 6C9.1 6C10.2 6C11.1 6C12.2 6C15.2 6C16.1 6C19.2 6D1.2(CATHODE_D2) 6D2.2(CATHODE_D2) 6D3.2(CATHODE_D2) 6SMP1.G1 6SMP1.G2 6SMP1.G3 6SMP1.G4 6SMP1.G5 6SMP1.G6 6SMP1.G7 6SMP1.G8 6SMP1.G9 6SMP2.G1 6SMP2.G2 6SMP2.G3 6SMP2.G4 6SMP2.G5 6SMP2.G6 6SMP2.G7 6SMP2.G8 6SMP2.G9 6SMP3.G1 6SMP3.G2 6SMP3.G3 6SMP3.G4 6SMP3.G5 6SMP3.G6 6SMP3.G7 6SMP3.G8 6SMP3.G9 6U1.2(GND) 6U2.2(GND) ; also on sheet 2 5 8 11 14 17 23
DGND: 6BD34.1 6BD35.1 6C17.1 6C18.1 6C20.2 6C21.2 6C22.2 6C23.1 6C24.2 6C25.1 6C38.1 6C39.2 6C40.1 6C41.2 6C44.2 6C45.2 6C46.2 6C47.2 6C48.2 6C49.2 6C52.2 6C53.2 6C54.2 6C55.2 6C56.2 6C57.2 6C58.2 6C59.2 6C60.2 6C61.2 6C62.2 6C63.2 6C64.2 6C65.2 6C66.2 6C67.2 6C68.2 6C69.2 6C70.2 6C71.2 6C72.2 6C73.2 6C74.2 6C75.2 6C76.2 6C77.2 6C78.2 6C79.2 6C83.2 6C84.2 6C85.2 6C88.2 6C89.2 6C90.2 6C91.2 6C92.2 6C93.2 6C94.2 6C95.2 6C96.2 6C97.2 6C98.2 6C99.2 6C100.2 6C101.2 6C102.2 6C105.2 6C106.2 6C107.2 6C108.2 6C109.2 6C110.2 6C111.2 6C112.2 6C113.1 6C116.2 6C117.2 6C118.2 6C119.2 6C120.2 6C121.2 6C122.2 6C123.2 6C124.2 6C125.2 6C126.2 6C127.2 6C128.2 6C129.2 6C130.2 6C131.2 6C132.2 6C133.2 6C134.2 6C135.2 6C136.2 6C137.2 6C138.2 6C139.2 6C140.2 6C141.2 6C142.2 6C143.1 6C144.1 6C145.1 6C146.1 6C147.1 6C148.1 6C149.1 6C150.1 6C152.2 6C153.2 6J1.2 6J2.2 6J3.2 6J4.8 6R18.1 6R22.2 6R23.2 6R25.2 6R26.2 6R33.1 6R42.2 6R43.2 6R49.2 6R51.2 6R54.2 6R62.2 6R71.2 6R72.2 6R73.2 6ST5.2 6ST16.2 6ST17.2 6ST18.2 6ST19.2 6U3.4(GND) 6Y1.2 6Y1.4 S6_GND1.1(TP) S6_GND2.1(TP) S6_GND3.1(TP) S6_GND4.1(TP) SITE6.4(GND_SPS_DCORE) SITE6.30(GND) SITE6.74(GND_SPS_MEM) SITE6.99(GND_SPS_AUD) SITE6.EP(EPAD) SITE6.G1 SITE6.G2 SITE6.G3 SITE6.G4 SITE6.G5 SITE6.G6 SITE6.G7 SITE6.G8 SITE6.G9 SITE6.G10 SITE6.G11 SITE6.G12 SITE6.G13 SITE6.G14 SITE6.G15 SITE6.G16 SITE6.G17 SITE6.G18 SITE6.G19 SITE6.G20 SITE6.G21 SITE6.G22 SITE6.G23 SITE6.G24 SITE6.G25 SITE6.G26 SITE6.G27 SITE6.G28 SITE6.G29 SITE6.G30 SITE6.G31 SITE6.G32 SITE6.G33 ; also on sheet 2 3 4 5 6 7 8 9 10 11 12 13 14 15 16 17 18 19 23 24 25 26 27 29 30 32 34 37 39
S6_1_AOUT_LN: 6K10.4 6R45.1 6R67.1 6R68.1
S6_1_AOUT_LP: 6K10.5 6R69.1 6R70.1 6R75.1
S6_1_AOUT_RN: 6K14.4 6R47.1 6R63.1 6R64.1
S6_1_AOUT_RP: 6K14.5 6R65.1 6R66.1 6R74.1
S6_1_SPI_CLK: 6R15.1 6U3.6(SCLK)
S6_1_SPI_CS: 6R10.2 6U3.1(CS#)
S6_1_SPI_DATA0: 6R17.1 6U3.5(SI/SIO0)
S6_1_SPI_DATA1: 6R11.2 6U3.2(SO/SIO1)
S6_1_SPI_DATA2: 6R14.2 6R16.2 6R18.2 6U3.3(WP#/SIO2)
S6_1_SPI_DATA3: 6R12.1 6R13.1 6U3.7(RST#/SIO3)
S6_1_VDD09: 6BD1.1 6BD2.1 6BD37.1 6C60.1 6R48.2 6R76.1 6R77.1 6R78.1 6R79.1 6ST13.2
S6_1_VDD18_A: 6K26.2 6K26.5 6R50.1 S6_1V3.1(TP)
S6_1_VDD18_D: 6C113.2 6R53.2 6R81.1 6R82.1 6R83.1 6ST15.1
S6_2_AOUT_LN: 6K12.4 6R68.2
S6_2_AOUT_LP: 6K12.5 6R69.2
S6_2_AOUT_RN: 6K15.4 6R64.2
S6_2_AOUT_RP: 6K15.5 6R65.2
S6_2_VDD18_A: 6BD16.1 6BD17.1 6BD19.1 6BD20.1 6C89.1 6R50.2
S6_ATX_VD0V9: 6C65.1 6C66.1 6K21.6 6ST3.2 ; also on sheet 27
S6_ATX_VD1V8: 6J7.1 6J8.1 6J9.1 ; also on sheet 27
S6_ATX_VD33: 6BD33.1 6C131.1 6C132.1 6C133.1 6C134.1 6C135.1 6J6.2 ; also on sheet 27
S6_AVCC_DRV: 6C75.1 6C110.1 6R55.2 6ST14.1 SITE6.53(AVCC_DRV)
S6_CHIP_EN_1: 6R34.2 6SW5.1
S6_DPS_F001: 6C120.1 6C121.1 6J9.2 6K29.6 6ST11.2
S6_DPS_F002: 6C92.1 6C93.1 6C94.1 6C95.1 6J8.2 6K26.6 6ST8.2
S6_DPS_F004: 6C140.1 6C141.1 6J7.2 6K20.6 6ST12.2
S6_DPS_F006: 6C68.1 6C69.1 6C70.1 6C71.1 6C72.1 6K23.3 6K23.6 6ST4.2 S6_VD33_ALL1.1(TP)
S6_DPS_GS001: 6ST19.1
S6_DPS_GS002: 6ST18.1
S6_DPS_GS003-1: 6ST16.1
S6_DPS_GS004: 6ST17.1
S6_DPS_GS006: 6ST5.1
S6_DPS_S001: 6ST11.1
S6_DPS_S002: 6ST8.1
S6_DPS_S003-1: 6ST3.1
S6_DPS_S004: 6ST12.1
S6_DPS_S006: 6ST4.1
S6_HSDM: 6K5.8 SITE6.79(HSDM)
S6_HSDP: 6K5.2 SITE6.78(HSDP)
S6_LPC_001: 6K36.7
S6_LPC_002: 6K36.2
S6_LPC_003: 6K11.2
S6_LPC_005: 6K14.2
S6_LPC_006: 6K18.4
S6_LPC_007: 6K1.4
S6_LPC_008: 6K35.2
S6_LPC_009: 6K38.3
S6_LPC_010: 6K34.7
S6_LPC_012: 6K37.3
S6_LPC_013+: 6K5.3 6K7.2
S6_LPC_013-: 6K5.7 6K7.8
S6_LPC_016: 6K2.5
S6_LPC_017: 6K35.7
S6_LPC_019: 6K12.2
S6_LPC_021: 6K1.5
S6_LPC_022: 6K15.2
S6_LPC_023: 6K3.4
S6_LPC_024: 6J4.2 6R35.1 SITE6.69(UART2_TXD/TEST_MODE_SEL/DMIC0_CLK/GPIOF_1/PB[22])
S6_LPC_025: 6J4.1 6R34.1 SITE6.71(CHIP_EN)
S6_LPC_026: 6K2.4
S6_LPC_027: 6K10.2
S6_LPC_028: 6K10.7
S6_LPC_029: 6K13.7
S6_LPC_030: 6K16.2
S6_LPC_032: 6K15.7
S6_LPC_033: 6K14.7
S6_LPC_034: 6K18.5
S6_LPC_035: 6K12.7
S6_LPC_036: 6K34.2
S6_LPC_038: 6K13.2
S6_LPC_039: 6K3.5
S6_LPC_040: 6K11.7
S6_LPC_041: 6J4.3 6R36.1 SITE6.68(UART2_RXD/BOOT_SEL/DMIC0_DATA/GPIOF_0/PB[21])
S6_LPC_042: 6C18.2 SITE6.50(MIC_BIAS2/GPIOC_13/PA[31])
S6_LPC_043: 6K33.3
S6_LPC_044: 6J4.5 6R39.1 SITE6.58(I2S3_DOUT1/DMIC_DATA2/ICFG1/GPIOD_4/PB[11])
S6_LPC_045: 6K39.3
S6_LPC_046: SITE6.67(I2S2_DIN3/I2S3_DOUT3/SPK_CLK/SPI0_CS/GPIOE_6/PB[20])
S6_LPC_047: 6J4.7 6R41.1 SITE6.18(GPIOB_7/PA[16]/ICFG3/SPI0_CS/UART0_RTS/HP_I2C2_SCL/ANT_SEL_N)
S6_LPC_048: 6K6.4
S6_LPC_049: SITE6.8(GPIOA_5/PA[5]/TOUCH5/ADC5/UART1_TXD/SPI1_MOSI/PWM4)
S6_LPC_050: SITE6.7(GPIOA_4/PA[4]/TOUCH4/ADC4/UART1_RXD/SPI1_MISO/PWM3/HP_I2C1_SCL)
S6_LPC_051: 6C17.2 SITE6.49(MIC_BIAS1/GPIOC_12/PA[30])
S6_LPC_052: 6C21.1 SITE6.48(AVCC)
S6_LPC_053: 6J4.4 6R37.1 SITE6.57(I2S3_DOUT0/DMIC_DATA1/ICFG0/BT_LOG/GPIOD_3/PB[10])
S6_LPC_054: 6K6.5
S6_LPC_055: SITE6.10(VBAT_MEAS)
S6_LPC_057: 6K9.4
S6_LPC_058: 6J4.6 6R40.1 SITE6.17(GPIOB_6/PA[15]/ICFG2/SPI0_CLK/UART0_CTS/HP_I2C2_SDA/ANT_SEL_P)
S6_LPC_059: 6K39.6
S6_LPC_060: SITE6.66(I2S2_DIN2/I2S3_DOUT2/SPK_DATA/SPI0_CK/GPIOE_5/PB[19])
S6_LPC_A_015: 6K8.4
S6_LPC_A_020: 6K8.5
S6_LPC_B_031: 6K4.4
S6_LPC_B_037: 6K4.5
S6_LX_AUD: 6K20.3 SITE6.100(LX_AUD)
S6_LX_AUD_CH_1: 6K20.4 6K38.2
S6_LX_AUD_CH_2: 6K38.4 6ST14.2
S6_LX_DCORE: 6K21.3 SITE6.3(LX_DCORE)
S6_LX_DCORE_CH: 6K21.4 6K37.2
S6_LX_MEM: 6K29.3 SITE6.75(LX_MEM)
S6_LX_MEM_CH_1: 6K29.4 6K33.2
S6_LX_MEM_CH_2: 6K33.4 6ST15.2
S6_MIPITX_CKN: 6K36.6 SITE6.82(MIPITX_CKN)
S6_MIPITX_CKP: 6K36.3 SITE6.83(MIPITX_CKP)
S6_MIPITX_DATAN_0: 6K34.6 SITE6.85(MIPITX_DATAN_0)
S6_MIPITX_DATAN_1: 6K35.6 SITE6.80(MIPITX_DATAN_1)
S6_MIPITX_DATAP_0: 6K34.3 SITE6.86(MIPITX_DATAP_0)
S6_MIPITX_DATAP_1: 6K35.3 SITE6.81(MIPITX_DATAP_1)
S6_PA2: 6K18.3 SITE6.5(GPIOA_2/PA[2]/TOUCH2/ADC2/UART0_RXD/SPI1_CS)
S6_PA3: 6K18.6 SITE6.6(GPIOA_3/PA[3]/TOUCH3/ADC3/UART0_TXD/SPI1_CLK/LEDC/HP_I2C1_SDA)
S6_PA9_CH: 6K39.2 SITE6.12(GPIOB_0/PA[9])
S6_PA10_CH: 6K39.7 SITE6.13(GPIOB_1/PA[10])
S6_PA13: 6K6.3 SITE6.15(GPIOB_4/PA[13]/SWD_DATA/SPI0_MOSI/UART0_RXD/HP_I2C1_SDA)
S6_PA13_UART_RX: 6K6.2 6R27.1
S6_PA13_UART_RX_1: 6J2.3 6R27.2
S6_PA14: 6K6.6 SITE6.16(GPIOB_5/PA[14]/SWD_CLK/SPI0_MISO/UART0_TXD/HP_I2C1_SCL)
S6_PA14_UART_TX: 6K6.7 6R28.1
S6_PA14_UART_TX_1: 6J2.4 6R28.2
S6_PA15_1: 6R40.2 6SW5.6
S6_PA16_1: 6R41.2 6SW5.7
S6_PA20: 6K15.6 SITE6.45(MIC1_P/GPIOC_2/PA[20])
S6_PA21: 6K15.3 SITE6.46(MIC1_N/GPIOC_3/PA[21])
S6_PA22: 6K11.6 SITE6.43(MIC2_P/GPIOC_4/PA[22])
S6_PA23: 6K11.3 SITE6.44(MIC2_N/GPIOC_5/PA[23])
S6_PA24: 6K12.6 SITE6.41(MIC3_P/I2C_SDA/GPIOC_6/PA[24])
S6_PA25: 6K12.3 SITE6.42(MIC3_N/I2C_SCL/GPIOC_7/PA[25])
S6_PA28: 6K13.6 SITE6.39(MIC5_P/ANT_SEL_P/GPIOC_10/PA[28])
S6_PA29: 6K13.3 SITE6.40(MIC5_N/ANT_SEL_N/GPIOC_11/PA[29])
S6_PB3: 6K10.6 SITE6.52(AOUT_LP/GPIOC_17/PB[3])
S6_PB3_AOUT_LP_2: 6K13.5 6R70.2
S6_PB4: 6K10.3 SITE6.51(AOUT_LN/GPIOC_18/PB[4])
S6_PB4_AOUT_LN_2: 6K13.4 6R67.2
S6_PB5: 6K14.6 SITE6.54(AOUT_RP/GPIOC_19/PB[5])
S6_PB5_AOUT_RP_2: 6K11.5 6R66.2
S6_PB6: 6K14.3 SITE6.55(AOUT_RN/GPIOC_20/PB[6])
S6_PB6_AOUT_RN_2: 6K11.4 6R63.2
S6_PB10_1: 6R37.2 6SW5.4
S6_PB11_1: 6R39.2 6SW5.5
S6_PB21_1: 6R36.2 6SW5.3
S6_PB22_1: 6R35.2 6SW5.2
S6_PB23: 6C144.2 6K4.3 6R57.1 SITE6.72(UART_LOG_RXD/OTP_BYPASS/GPIOF_2/PB[23])
S6_PB23_1: 6R57.2 6SW6.1
S6_PB23_SICK: 6K4.2 6R20.1
S6_PB23_SICK_1: 6J1.3 6R20.2
S6_PB24: 6C143.2 6K4.6 6R58.1 SITE6.73(UART_LOG_TXD/UART_DOWNLOAD/GPIOF_3/PB[24])
S6_PB24_1: 6R58.2 6SW6.2
S6_PB24_SIDD: 6K4.7 6R21.1
S6_PB24_SIDD_1: 6J1.4 6R21.2
S6_PB25: 6K8.3 6R59.1 SITE6.96(SPI0_CLK/SWD_CLK/SD_D2/ICFG2/GPIOG_0/PB[25])
S6_PB25_1: 6R59.2 6SW6.3
S6_PB25_I2C_SCL: 6K8.2 6R31.1
S6_PB25_I2C_SCL_1: 6J3.3 6R31.2
S6_PB26: 6K8.6 6R60.1 SITE6.97(SPI0_CS/SWD_DATA/SD_D3/ICFG3/GPIOG_1/PB[26])
S6_PB26_1: 6R60.2 6SW6.4
S6_PB26_I2C_SDA: 6K8.7 6R32.1
S6_PB26_I2C_SDA_1: 6J3.4 6R32.2
S6_RF_A: 6C13.1 6C14.1 6C15.1 6D3.1(CATHODE_D1) 6SMP3.1
S6_RF_G: 6C6.1 6C7.1 6C8.1 6D2.1(CATHODE_D1) 6SMP2.1
S6_RFIN_A: 6C16.2 6R9.1 SITE6.29(RFIN_A/GND_(<750um))
S6_RFIN_G: 6C9.2 6R5.1 SITE6.31(RFIN_G/GND)
S6_RFIO_A: 6C11.2 6R6.1 SITE6.28(RFIO_A__(<750um))
S6_RFIO_BT: 6C1.2 6R1.1 SITE6.37(RFIO_BT)
S6_RFIO_G: 6C4.2 6R2.1 SITE6.32(RFIO_G)
S6_RREF_MEM: 6K9.3 6R43.1 SITE6.60(RREF_MEM)
S6_SPI_CLK: 6K1.7 6R15.2
S6_SPI_CLK/PB28: 6K1.6 SITE6.90(SPI_FLASH_CLK/SD_CLK/GPIOG_3/PB[28])
S6_SPI_CS: 6K3.2 6R10.1
S6_SPI_CS/PC0: 6K3.3 SITE6.95(SPI_FLASH_CS/UART1_CTS/SD_CD/GPIOG_7/PC[0])
S6_SPI_D0/PB29: 6K1.3 SITE6.91(SPI_FLASH_DATA0/UART1_RXD/SD_D0/GPIOG_4/PB[29])
S6_SPI_D1/PB31: 6K3.6 SITE6.94(SPI_FLASH_DATA1/UART1_RTS/SD_WP/GPIOG_6/PB[31])
S6_SPI_D2/PB30: 6K2.6 SITE6.92(SPI_FLASH_DATA2/UART1_TXD/SD_D1/GPIOG_5/PB[30])
S6_SPI_D3/PB27: 6K2.3 SITE6.89(SPI_FLASH_DATA3/SD_CMD/GPIOG_2/PB[27])
S6_SPI_DATA0: 6K1.2 6R17.2
S6_SPI_DATA1: 6K3.7 6R11.1
S6_SPI_DATA2: 6K2.7 6R16.1
S6_SPI_DATA3: 6K2.2 6R13.2
S6_U1_VC1: 6K39.5 6U1.4(VCTL)
S6_U2_VC1: 6K39.4 6U2.4(VCTL)
S6_VA09_MIPI: 6BD37.2 6C152.1 SITE6.84(VA09_MIPI/VA09_CK/VA09_DA)
S6_VA09_PLL: 6BD1.2 6C44.1 SITE6.11(VA09_PLL/VD09_CORE0)
S6_VA09_USB: 6BD2.2 6C45.1 SITE6.77(VA09_USB)
S6_VA13_AFE: 6BD20.2 6C88.1 SITE6.19(VA13_AFE)
S6_VA13_SYN: 6BD16.2 6C78.1 SITE6.23(VR13_SYN)
S6_VA33_SYN: 6BD13.2 6C64.1 SITE6.24(VR33_SYN)
S6_VA33_XTAL: 6BD5.2 6C48.1 SITE6.20(VA33_XTAL)
S6_VD09_CORE1: 6C47.1 6R76.2 SITE6.56(VD09_CORE1/VD09MEM0)
S6_VD09_CORE2: 6C49.1 6R77.2 SITE6.64(VD09_CORE2/VD09_MEM1)
S6_VD09_CORE3: 6C54.1 6R78.2 SITE6.87(VD09_CORE3/VA09_PLL)
S6_VD09_CORE4: 6C58.1 6R79.2 SITE6.98(VD09_CORE4)
S6_VD13_FE: 6BD19.2 6C85.1 SITE6.36(VD13_FE)
S6_VD13_RF: 6BD17.2 6C79.1 SITE6.25(VD13_RF)
S6_VD33_ALL: 6BD3.1 6BD5.1 6BD7.1 6BD9.1 6BD11.1 6BD12.1 6BD13.1 6BD15.1 6BD18.1 6BD21.1 6BD22.1 6BD23.1 6BD28.1 6BD29.1 6BD30.1 6BD31.1 6BD32.1 6BD36.1 6C67.1 6C96.1 6C101.1 6C122.1 6C129.1 6J5.1 6J6.1 6K23.2 6K23.7
S6_VD33_CM_BT: 6BD21.2 6C90.1 6C91.1 SITE6.35(VD33_CM_BT)
S6_VD33_EX_FLASH: 6BD32.2 6C22.1 6C127.1 6C128.1 6R12.2 6R14.1 6U3.8(VCC)
S6_VD33_IO0: 6BD7.2 6C52.1 SITE6.9(VA33_PLL/VD33_IO0)
S6_VD33_IO2: 6BD9.2 6C56.1 SITE6.59(VD33_IO2/VD33_MEM)
S6_VD33_IO3: 6BD11.2 6C59.1 SITE6.70(VD33_IO3/VDD_IO4/VA33_USB)
S6_VD33_IO6: 6BD12.2 6C61.1 SITE6.88(VD33_IO6/VDD33_IO5/VD33_FLASH)
S6_VD33_SPS_AUD: 6BD30.2 6C123.1 6C124.1 SITE6.1(VD33_SPS_AUD)
S6_VD33_SPS_DCORE: 6BD28.2 6C111.1 6C112.1 SITE6.2(VD33_SPS_DCORE)
S6_VD33_SPS_MEM: 6BD31.2 6C125.1 6C126.1 SITE6.76(VD33_SPS_MEM)
S6_VD33PA_A: 6BD23.2 6C99.1 6C100.1 SITE6.27(VD33PA_A)
S6_VD33PA_BT: 6BD18.2 6C83.1 6C84.1 SITE6.38(VD33PA_BT)
S6_VD33PA_G: 6BD15.2 6C76.1 6C77.1 SITE6.33(VD33PA_G)
S6_VD33PAD_A: 6BD22.2 6C97.1 6C98.1 SITE6.26(VD33PAD_A)
S6_VD33PAD_G: 6BD36.2 6C73.1 6C74.1 SITE6.34(VD33PAD_G)
S6_VD1833_IO1: 6BD3.2 6C46.1 SITE6.14(VD1833_IO1)
S6_VD1833_SDIO: 6BD29.2 6C118.1 6C119.1 SITE6.93(VD1833_SDIO)
S6_VD_MEM0: 6C102.1 6R81.2 SITE6.61(VD_MEM0)
S6_VD_MEM1: 6C105.1 6R82.2 SITE6.62(VD_MEM1)
S6_VD_MEM2: 6C107.1 6R83.2 SITE6.65(VD_MEM2)
S6_VDD09: 6K22.2 6K22.5 6K31.4 6R48.1 S6_VDD09.1(TP)
S6_VDD09_CH: 6K37.4 6ST13.1
S6_VDD18_A: 6K25.2 6K25.5 6K26.3 6K32.4 6R55.1 S6_VDD18_A.1(TP)
S6_VDD18_D: 6K28.2 6K28.5 6K30.4 6R29.2 6R53.1 S6_VDD18_D.1(TP)
S6_VDD33: 6BD33.2 6C130.1 6R19.1 6R24.1 6R30.1 6R38.2 6R61.2 6U1.6(VDD) 6U2.6(VDD)
S6_VDD33_J1: 6J1.1 6R19.2
S6_VDD33_J2: 6J2.1 6R24.2
S6_VDD33_J3: 6J3.1 6R30.2
S6_VREF_DRAM: 6C153.1 6K16.3 SITE6.63(VREF_DRAM/NC(PSRAM))
S6_XI: 6C25.2 6Y1.1 SITE6.22(XI)
S6_XO: 6C23.2 6Y1.3 SITE6.21(XO)
S7_LPC_009: 6K38.6
S7_LPC_012: 6K37.6
S7_LPC_043: 6K33.6
S7_LX_AUD_CH_1: 6K38.7 ; also on sheet 25
S7_LX_AUD_CH_2: 6K38.5 ; also on sheet 25
S7_LX_DCORE_CH: 6K37.7 ; also on sheet 25
S7_LX_MEM_CH_1: 6K33.7 ; also on sheet 25
S7_LX_MEM_CH_2: 6K33.5 ; also on sheet 25
S7_VDD09_CH: 6K37.5 ; also on sheet 25
S4567_CBIT_001: 6K7.9(V-) ; also on sheet 14 17 23
S4567_CBIT_002: 6K37.8(V-) ; also on sheet 14 16
S4567_CBIT_003: 6K6.8(V-) ; also on sheet 14 17 23
S4567_CBIT_004: 6K2.8(V-) ; also on sheet 14 17 23
S4567_CBIT_005: 6K3.8(V-) ; also on sheet 14 17 23
S4567_CBIT_006: 6K35.8(V-) ; also on sheet 14 15 18 24
S4567_CBIT_007: 6K33.8(V-) ; also on sheet 14 16
S4567_CBIT_008: 6K30.8(V-) ; also on sheet 14 16 19 25
S4567_CBIT_009: 6K32.8(V-) ; also on sheet 14 16 19 25
S4567_CBIT_010: 6K31.8(V-) ; also on sheet 14 16 19 25
S4567_CBIT_011: 6K29.8(V-) ; also on sheet 14 16 19 25
S4567_CBIT_012: 6K28.8(V-) ; also on sheet 14 16 19 25
S4567_CBIT_013: 6K8.8(V-) ; also on sheet 14 17 23
S4567_CBIT_014: 6K26.8(V-) ; also on sheet 14 16 19 25
S4567_CBIT_015: 6K34.8(V-) ; also on sheet 14 15 18 24
S4567_CBIT_016: 6K16.8(V-) ; also on sheet 14 17 23
S4567_CBIT_017: 6K21.8(V-) ; also on sheet 14 16 19 25
S4567_CBIT_018: 6K18.8(V-) ; also on sheet 14 15 18 24
S4567_CBIT_019: 6K22.8(V-) ; also on sheet 14 16 19 25
S4567_CBIT_020: 6K9.8(V-) ; also on sheet 14 17 23
S4567_CBIT_022: 6K19.8(V-) ; also on sheet 14 15 18 24
S4567_CBIT_023: 6K23.8(V-) ; also on sheet 14 16 19 25
S4567_CBIT_024: 6K20.8(V-) ; also on sheet 14 16 19 25
S4567_CBIT_025: 6K13.8(V-) ; also on sheet 14 15 18 24
S4567_CBIT_026: 6K14.8(V-) ; also on sheet 14 15 18 24
S4567_CBIT_027: 6K15.8(V-) ; also on sheet 14 15 18 24
S4567_CBIT_028: 6K25.8(V-) ; also on sheet 14 16 19 25
S4567_CBIT_029: 6K10.8(V-) ; also on sheet 14 15 18 24
S4567_CBIT_030: 6K11.8(V-) ; also on sheet 14 15 18 24
S4567_CBIT_031: 6K12.8(V-) ; also on sheet 14 15 18 24
S4567_CBIT_032: 6K39.8(V-) ; also on sheet 14 17 23
S4567_CBIT_033: 6K1.8(V-) ; also on sheet 14 17 23
S4567_CBIT_034: 6K38.8(V-) ; also on sheet 14 16
S4567_CBIT_035: 6K5.9(V-) ; also on sheet 14 17 23
S4567_CBIT_036: 6K36.8(V-) ; also on sheet 14 15 18 24
S4567_CBIT_037: 6K4.8(V-) ; also on sheet 14 17 23
VP12: 6K1.1(V+) 6K2.1(V+) 6K3.1(V+) 6K4.1(V+) 6K5.1(V+) 6K6.1(V+) 6K7.1(V+) 6K8.1(V+) 6K9.1(V+) 6K10.1(V+) 6K11.1(V+) 6K12.1(V+) 6K13.1(V+) 6K14.1(V+) 6K15.1(V+) 6K16.1(V+) 6K18.1(V+) 6K19.1(V+) 6K20.1(V+) 6K21.1(V+) 6K22.1(V+) 6K23.1(V+) 6K25.1(V+) 6K26.1(V+) 6K28.1(V+) 6K29.1(V+) 6K30.1(V+) 6K31.1(V+) 6K32.1(V+) 6K33.1(V+) 6K34.1(V+) 6K35.1(V+) 6K36.1(V+) 6K37.1(V+) 6K38.1(V+) 6K39.1(V+) ; also on sheet 2 3 4 5 6 7 8 9 10 11 12 13 14 15 16 17 18 19 23 24 25 26 27 29 38
N27484303: 6C10.1 6R5.2 6U1.3(RF2)
N27484309: 6C7.2 6U1.5(ANT)
N27484312: 6R4.1 6U1.1(RF1)
N27484363: 6C6.2 6R3.2
N27484372: 6C19.1 6R9.2 6U2.1(RF1)
N27484379: 6C14.2 6U2.5(ANT)
N27484386: 6C12.1 6R6.2 6R7.1 6R8.2
N27484388: 6C13.2 6R7.2
N27484407: 6BD27.2 6C24.1 6K16.4
N27484417: 6K5.6 6R22.1
N27484419: 6K5.4 6R25.1
N27484422: 6R8.1 6U2.3(RF2)
N27484428: 6C5.1 6R2.2 6R3.1 6R4.2
N27484456: 6C2.1 6C3.1 6R1.2
N27484461: 6C2.2 6D1.1(CATHODE_D1) 6SMP1.1
N27484579: 6K7.6 6R23.1
N27484580: 6K7.4 6R26.1
N27484585: 6BD27.1 6R29.1 6R33.2
N27484712: 6C20.1 SITE6.47(VREF_AUDIO)
N27488311: 6K18.2 6K19.3
N27488312: 6K18.7 6K19.6
N27488315: 6C39.1 6K19.4
N27488316: 6C38.2 6K19.2
N27488319: 6C41.1 6K19.5
N27488320: 6C40.2 6K19.7
N27488351: 6R47.2 6R74.2
N27488433: 6R45.2 6R75.2
N27488449: 6C145.2 6K34.4
N27488450: 6C146.2 6K34.5
N27488457: 6C147.2 6K35.4
N27488458: 6C148.2 6K35.5
N27488461: 6C149.2 6K36.4
N27488462: 6C150.2 6K36.5
N27489549: 6K21.2 6L1.1
N27489579: 6K29.2 6L3.1
N27489580: 6C106.1 6C108.1 6C109.1 6K28.3 6L3.2
N27489591: 6K28.4 6R54.1
N27489595: 6C116.1 6C117.1 6K28.6 6K29.5
N27489618: 6C53.1 6C55.1 6C57.1 6K22.3 6L1.2
N27489630: 6K22.4 6R49.1
N27489634: 6C62.1 6C63.1 6K21.5 6K22.6
N27489749: 6K20.2 6L4.1
N27489750: 6C136.1 6C137.1 6C138.1 6K25.3 6L4.2
N27489761: 6K25.4 6R51.1
N27489763: 6C139.1 6C142.1 6K20.5 6K25.6
N27489869: 6K30.3 6R71.1
N27489871: 6K31.3 6R72.1
N27489873: 6K32.3 6R73.1
N27688167: 6R61.1 6SW6.6
N27688171: 6R62.1 6SW6.5
N27688293: 6R38.1 6SW5.10
N27688297: 6R42.1 6SW5.9

Not connected (* = marked no-connect by the designer): 6K7 3* 7*; 6K9 2* 5* 6* 7*; 6K16 5* 6* 7*; 6K20 7*; 6K21 7*; 6K22 7*; 6K23 4* 5*; 6K25 7*; 6K26 4* 7*; 6K28 7*; 6K29 7*; 6K30 2* 5* 6* 7*; 6K31 2* 5* 6* 7*; 6K32 2* 5* 6* 7*; 6SW5 8*; SITE6 GH1* GH2* GH3* GH4* NUT1* NUT2* NUT3* NUT4*

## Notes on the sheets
sheet 20
- WIFI/BT_RF
- place by Z-shape
- R3 and R4 Share PAD,
  Default R3
- C6 and C7 Share PAD,
  Default C6
- place by Z-shape
- place by Z-shape
- R7 and R8 Share PAD,
  Default R7
- C13 and C14 Share PAD,
  Default C13
- place by Z-shape
- place by Z-shape
- GND Shielding
- FLASH
- RF SW Channel  and PA9.10 share one Channel
- GND Shielding
- Mark On Board
- GND Shielding
- Debug
- 1.S0_VDD33
- 2.GND
- 3.S0_SICK
- DSSC
- 4.S0_SIDD
- SIC
- USB
- GND Shielding
- Mark On Board
- Debug
- 1.S0_VDD33
- 2.GND
- 3.S0_UART_RX
- 4.S0_UART_TX
- DIFF 90ohm
- UART
- DIFF 90ohm
- Debug
- Mark On Board
- XTAL
- VREF_DRAM
- GND Shielding
- 1.S0_VDD33
- Close To DUT
- 2.GND
- 3.S0_I2C_SCL
- DSSC
- 4.S0_I2C_SDA
- BT_I2C
- GND Shielding
- Mark On Board
- 1.S0_CHIP_EN
- 2.S0_PB22_TEST_MODE_SEL
- 3.S0_PB21_BOOT_SEL_FLASH
- 4.S0_PB10/ICFG0
- 5.S0_PB11/ICFG1
- 6.S0_PA15/ICFG2
- 7.S0_PA16/ICFG3
- 8.NC
- RREF
- Close To DUT
- Close to Relay
sheet 21
- AUDIO ADC Test
- MIPI Test
- GND Shielding
- GND Shielding
- CAP TOUCH Test
- GND Shielding
sheet 22
- CLOSE TO DUT
- POWER_VD09
- POWER_VD1833
- CLOSE TO DUT
- 110mA
- 5mA
- 33mA
- C48 TOP
- 20mA
- 102mA
- RELAY 2 SITE share
- 35mA
- 105mA
- 35mA
- 112mA
- 25mA
- 50mA
- Mark On Board : S0_VDD09
- C58 TOP
- 30mA
- 50mA
- 10mA
- C64 TOP
- 200mA
- CLOSE TO DUT
- 200mA
- POWER_VD18_AUD
- CLOSE TO DUT
- Mark On Board : S0_VDD18_A
- 200mA
- 100mA
- C75 TOP
- 50mA
- Mark On Board : S0_VDD33
- CLOSE TO DUT
- CLOSE TO DUT
- 45mA
- 60mA
- C78 TOP
- 80mA
- C79 TOP
- 45mA
- C97,C98 TOP
- RELAY 2 SITE share
- 300mA
- 25mA
- C88 TOP
- C99,C100 TOP
- POWER_VD18_DDR
- RELAY 2 SITE share
- CLOSE TO DUT
- CLOSE TO DUT
- 155mA
- 62mA
- C111,C112 TOP
- 62mA
- 30mA
- 62mA
- Mark On Board : S0_VDD18_D
- C107 TOP
- 107mA
- C123,C124 TOP
- 160mA
- C125,C126 TOP
- 50mA
- Calibration Loading SCH
